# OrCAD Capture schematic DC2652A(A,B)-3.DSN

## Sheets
1 PAGE1: size Custom
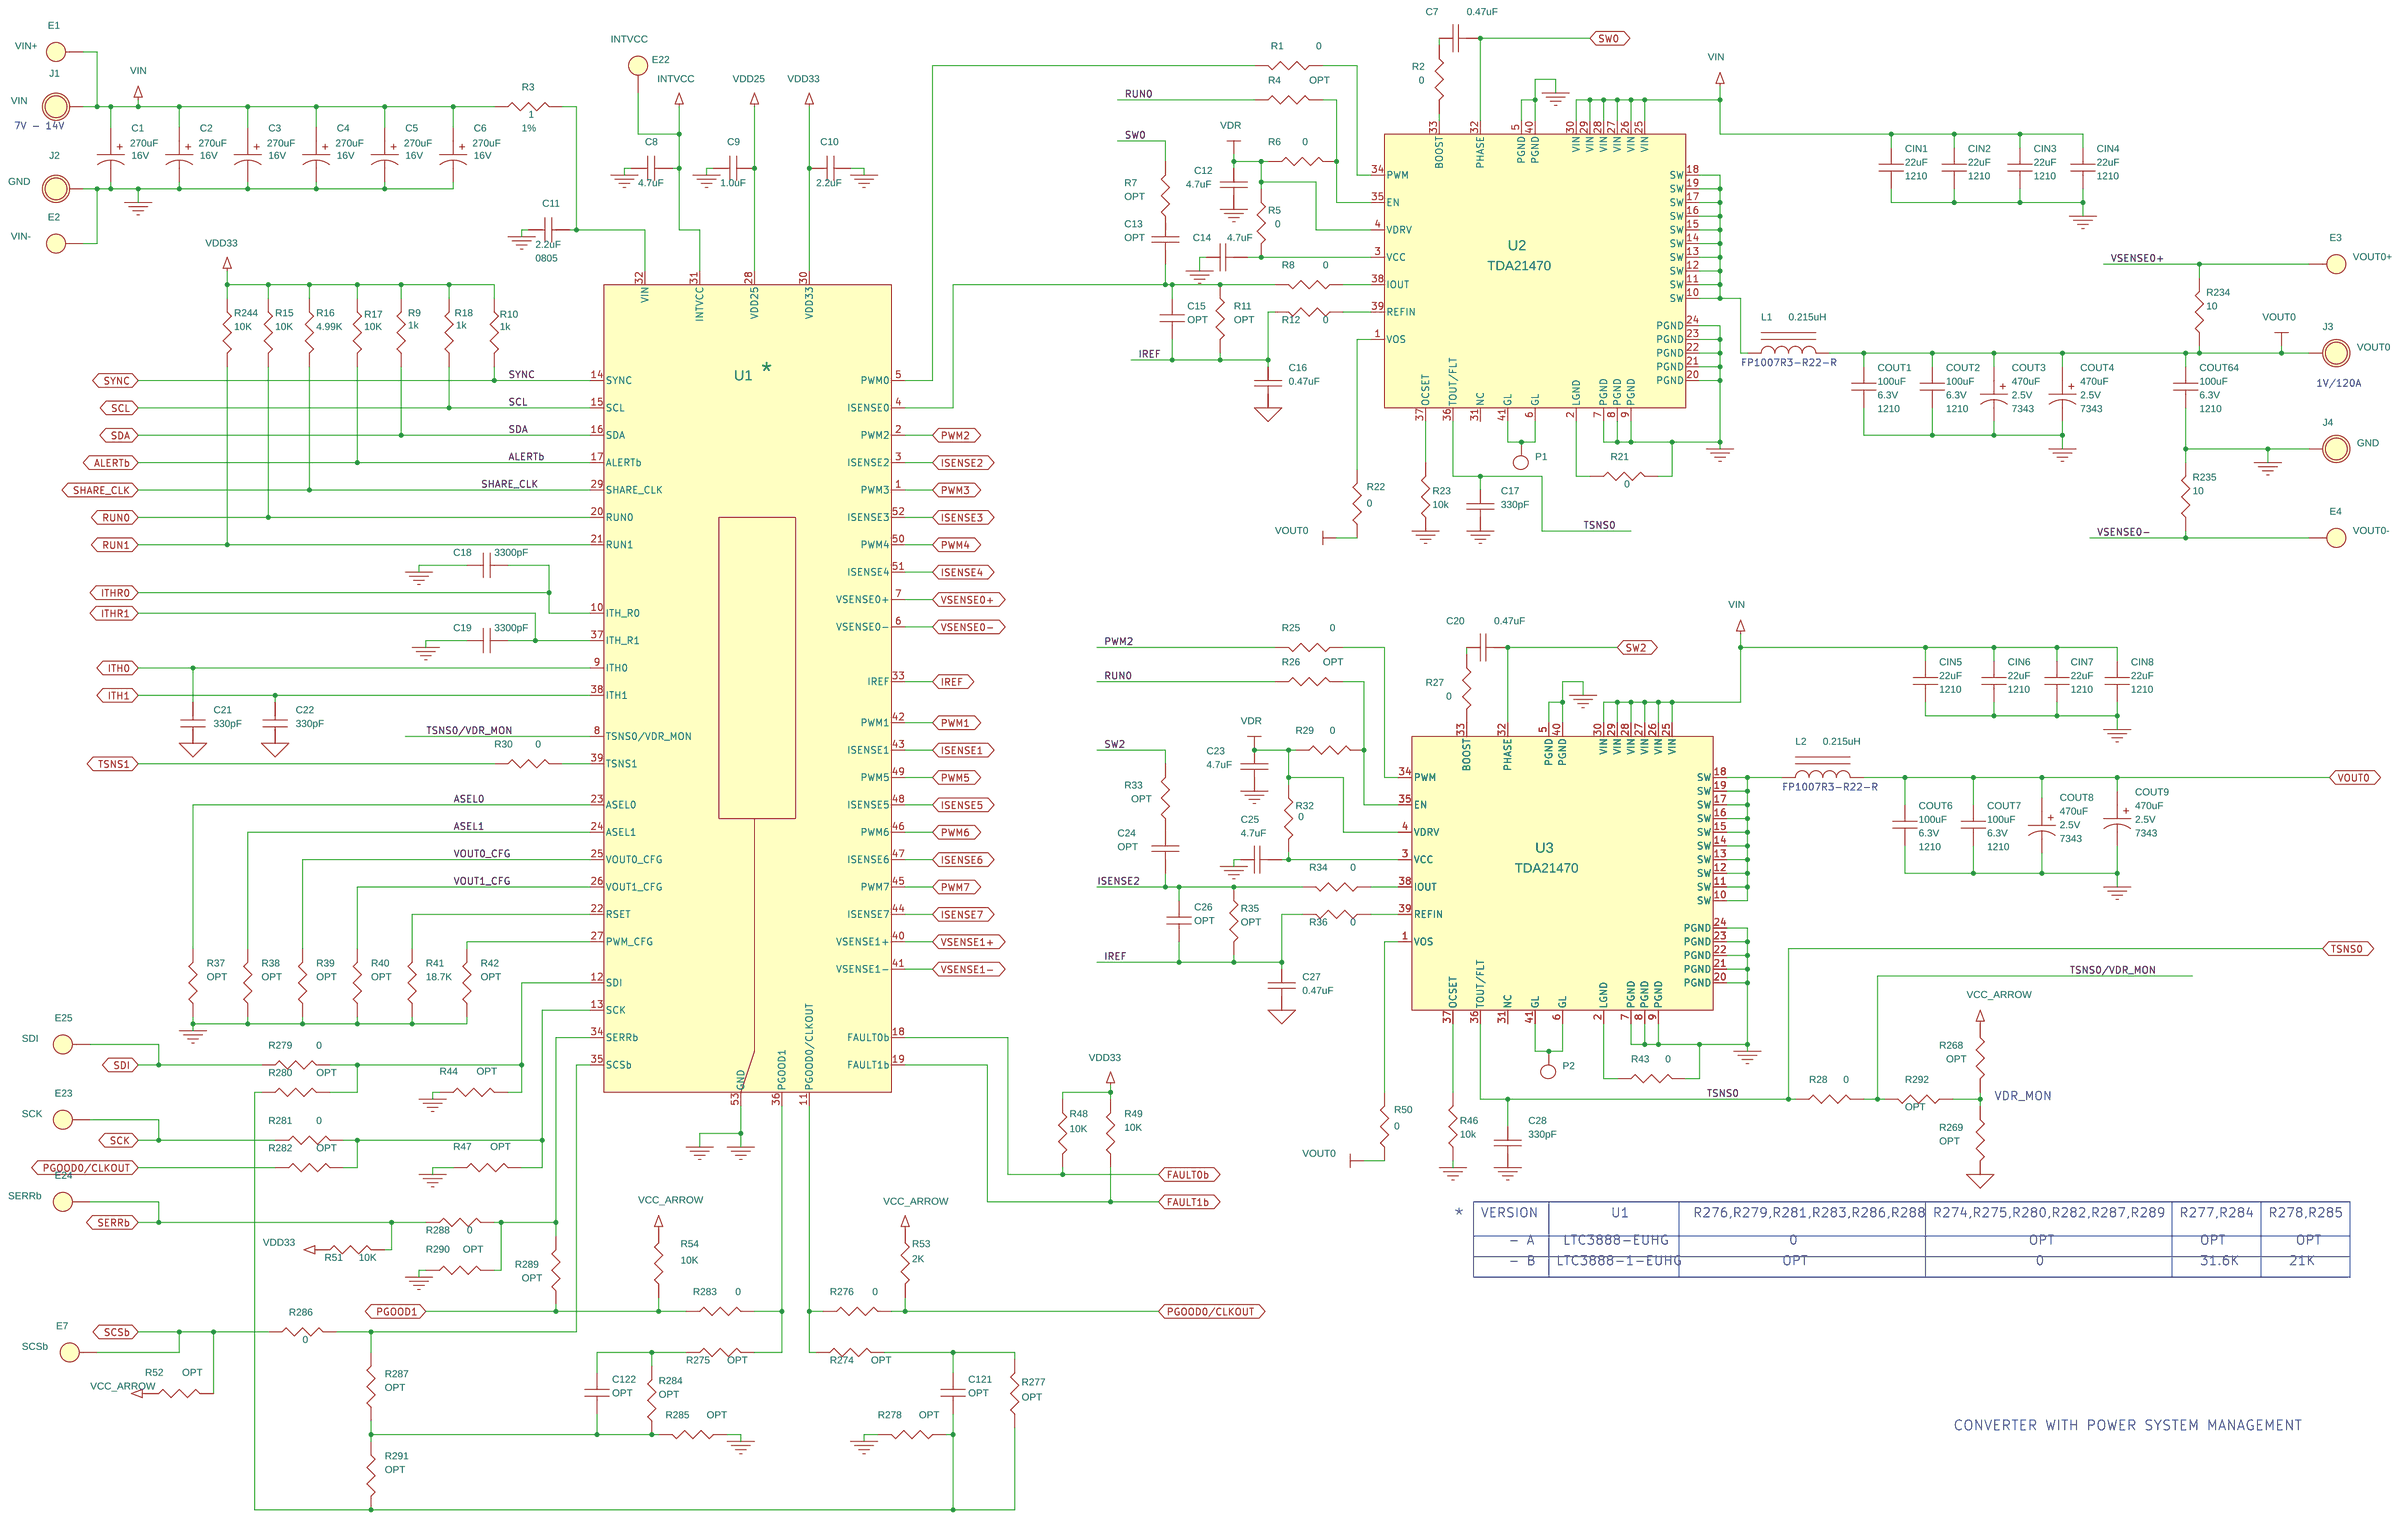
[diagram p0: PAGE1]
2 PAGE2: size Custom; note: 8-PHASE, DUAL OUTPUT SYNCHRONOUS BUCK
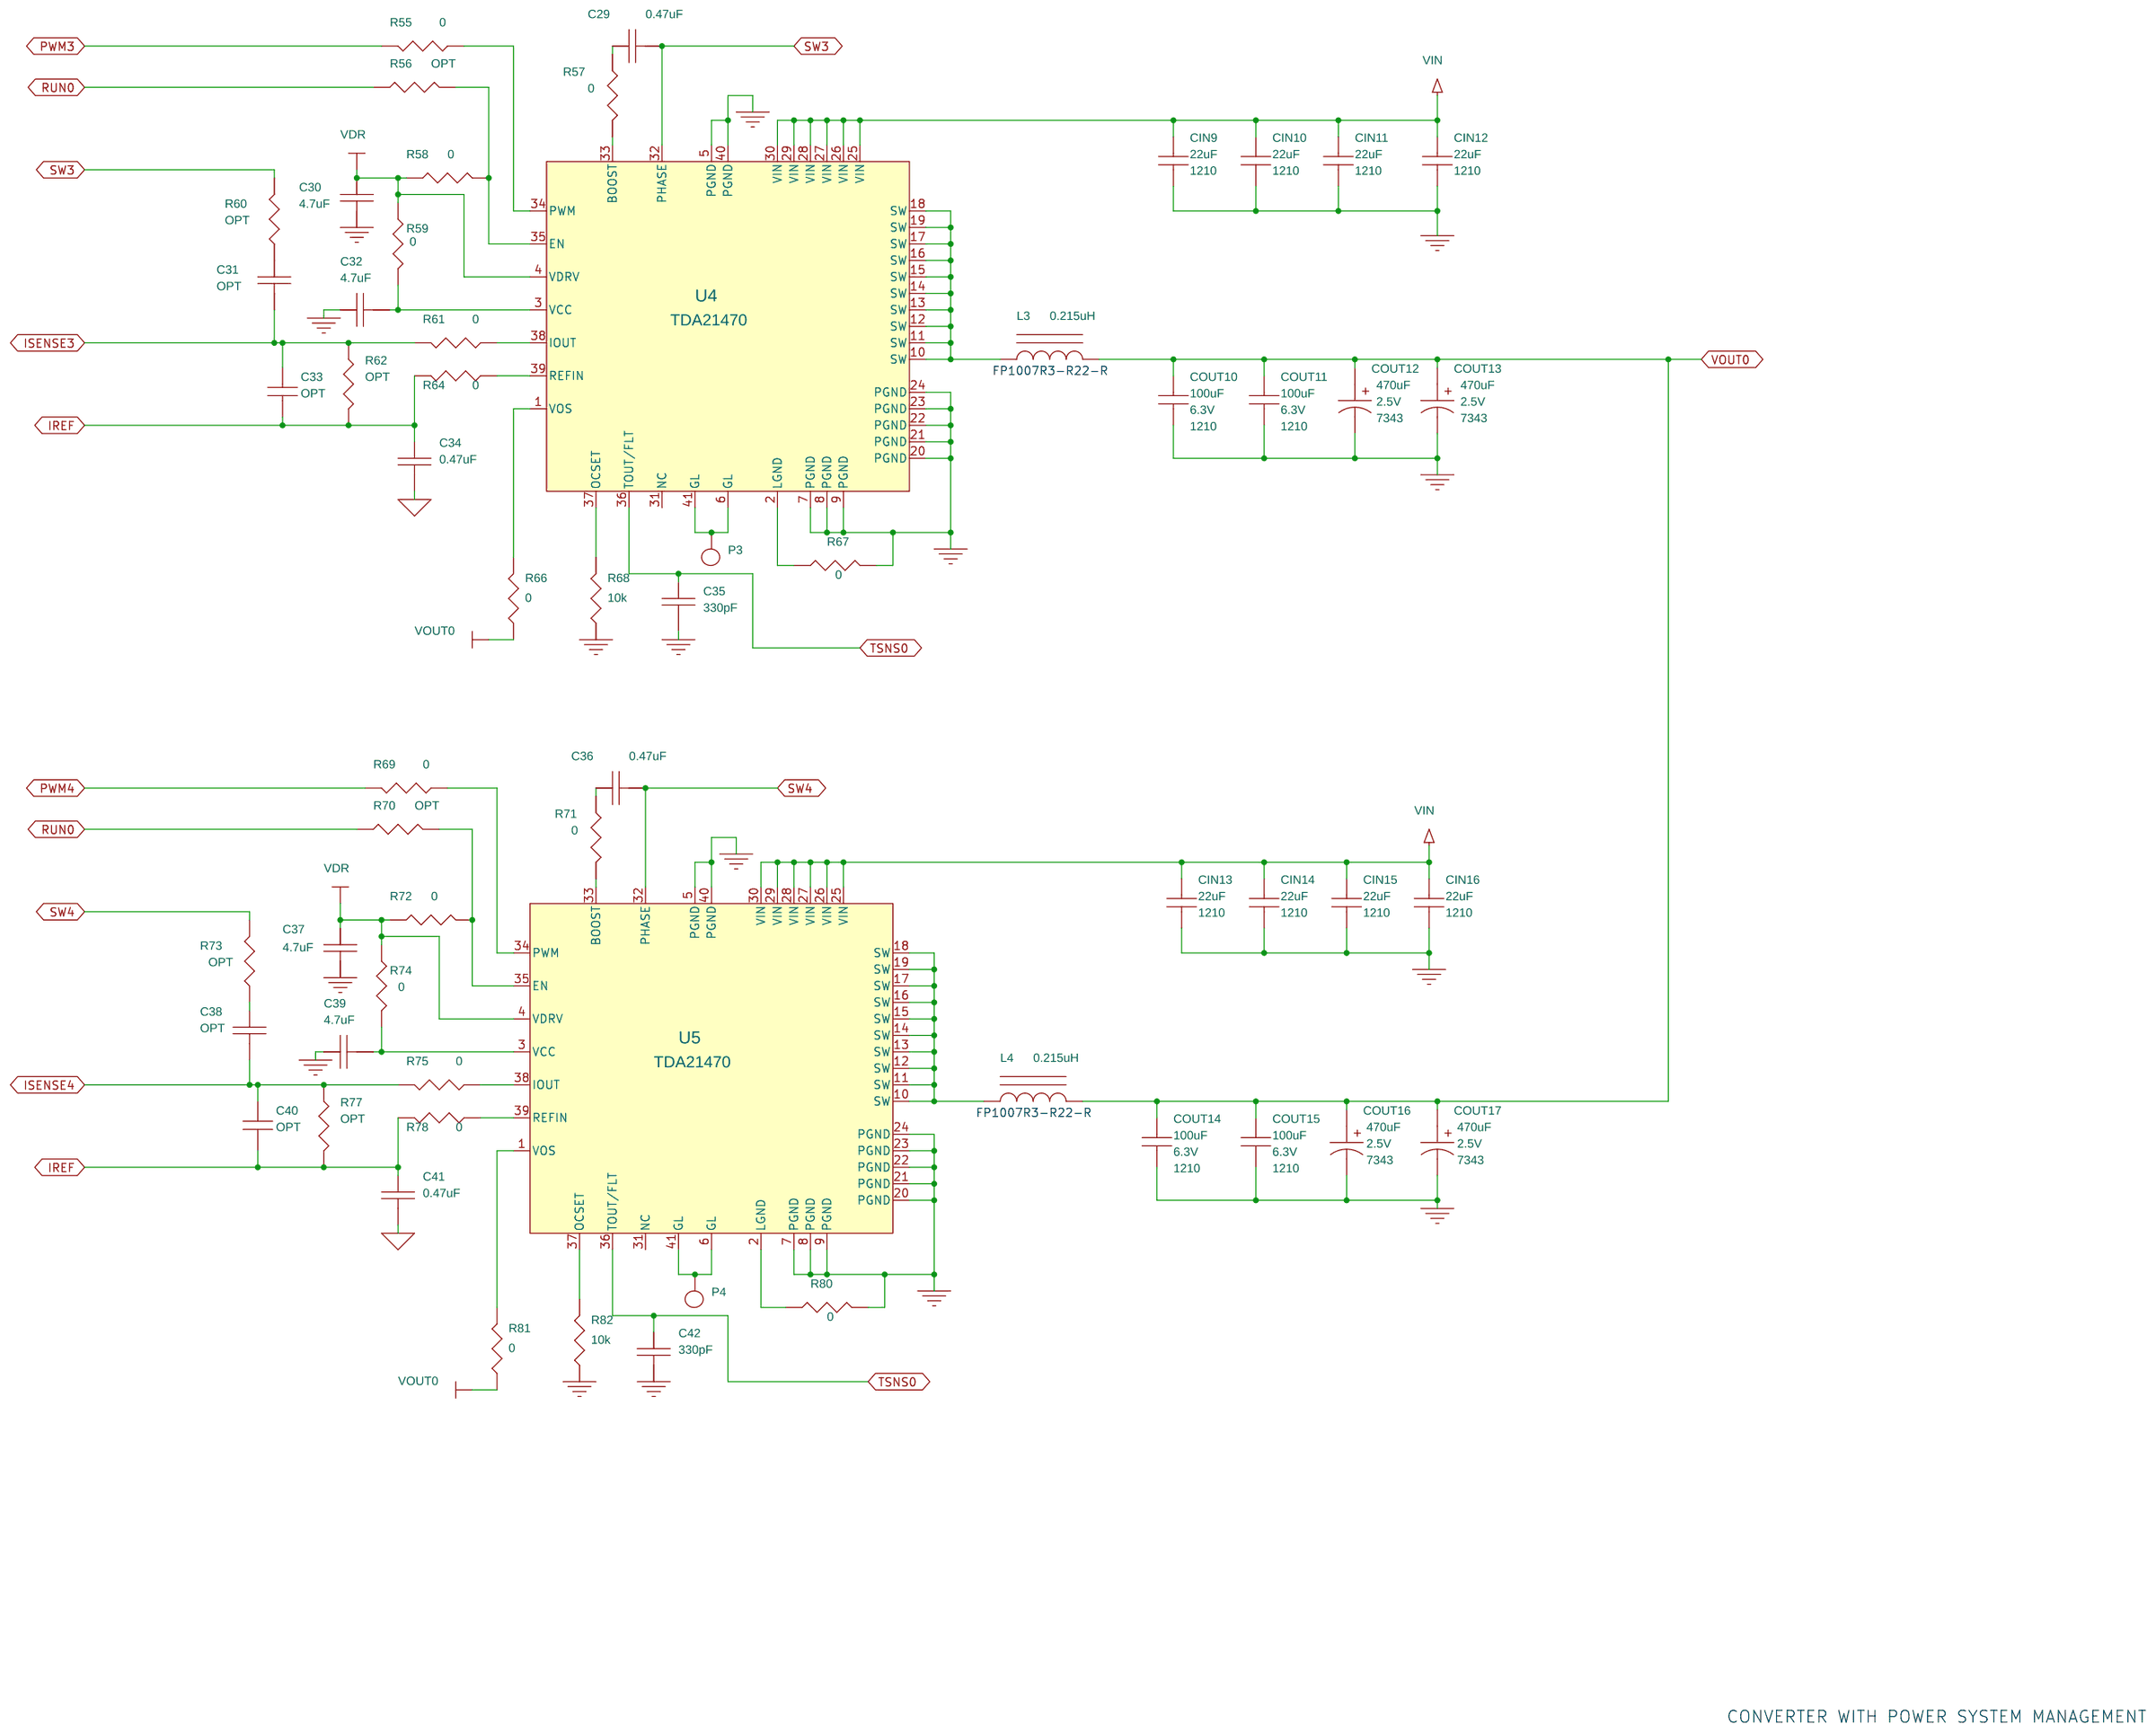
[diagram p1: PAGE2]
3 PAGE3: size Custom; note: 8-PHASE, DUAL OUTPUT SYNCHRONOUS BUCK
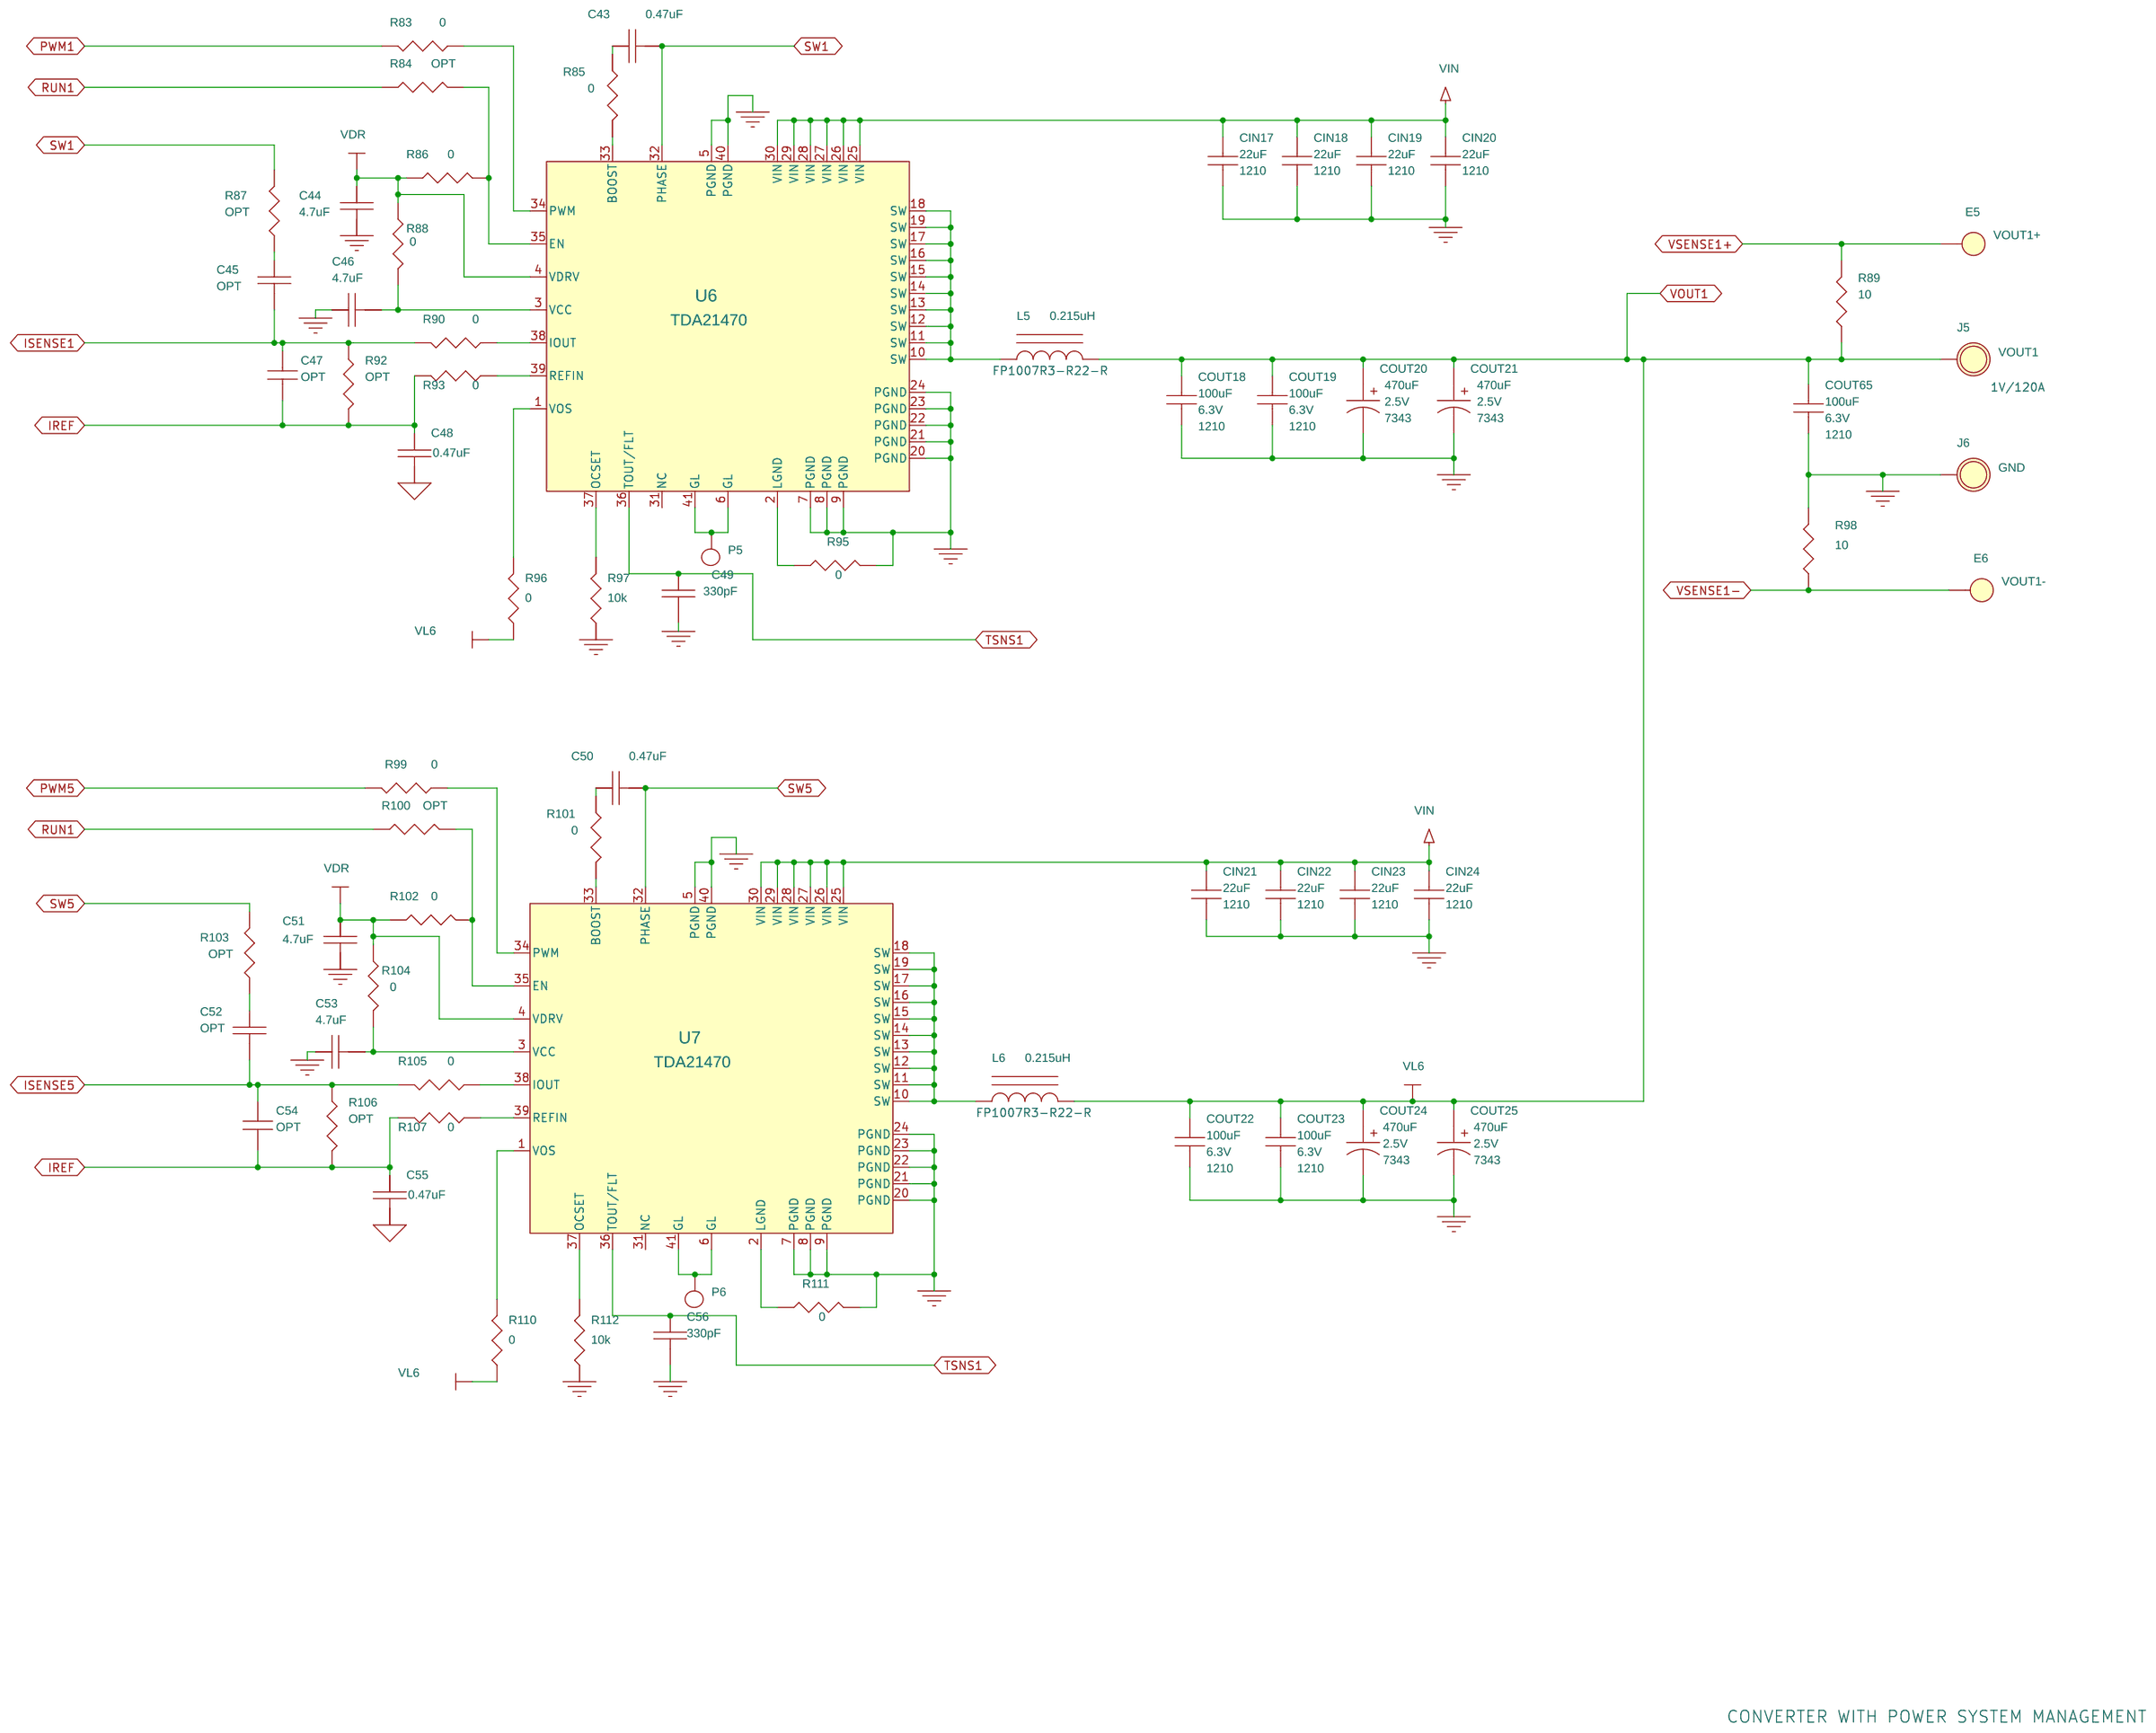
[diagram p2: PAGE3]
4 PAGE4: size Custom; note: 8-PHASE, DUAL OUTPUT SYNCHRONOUS BUCK
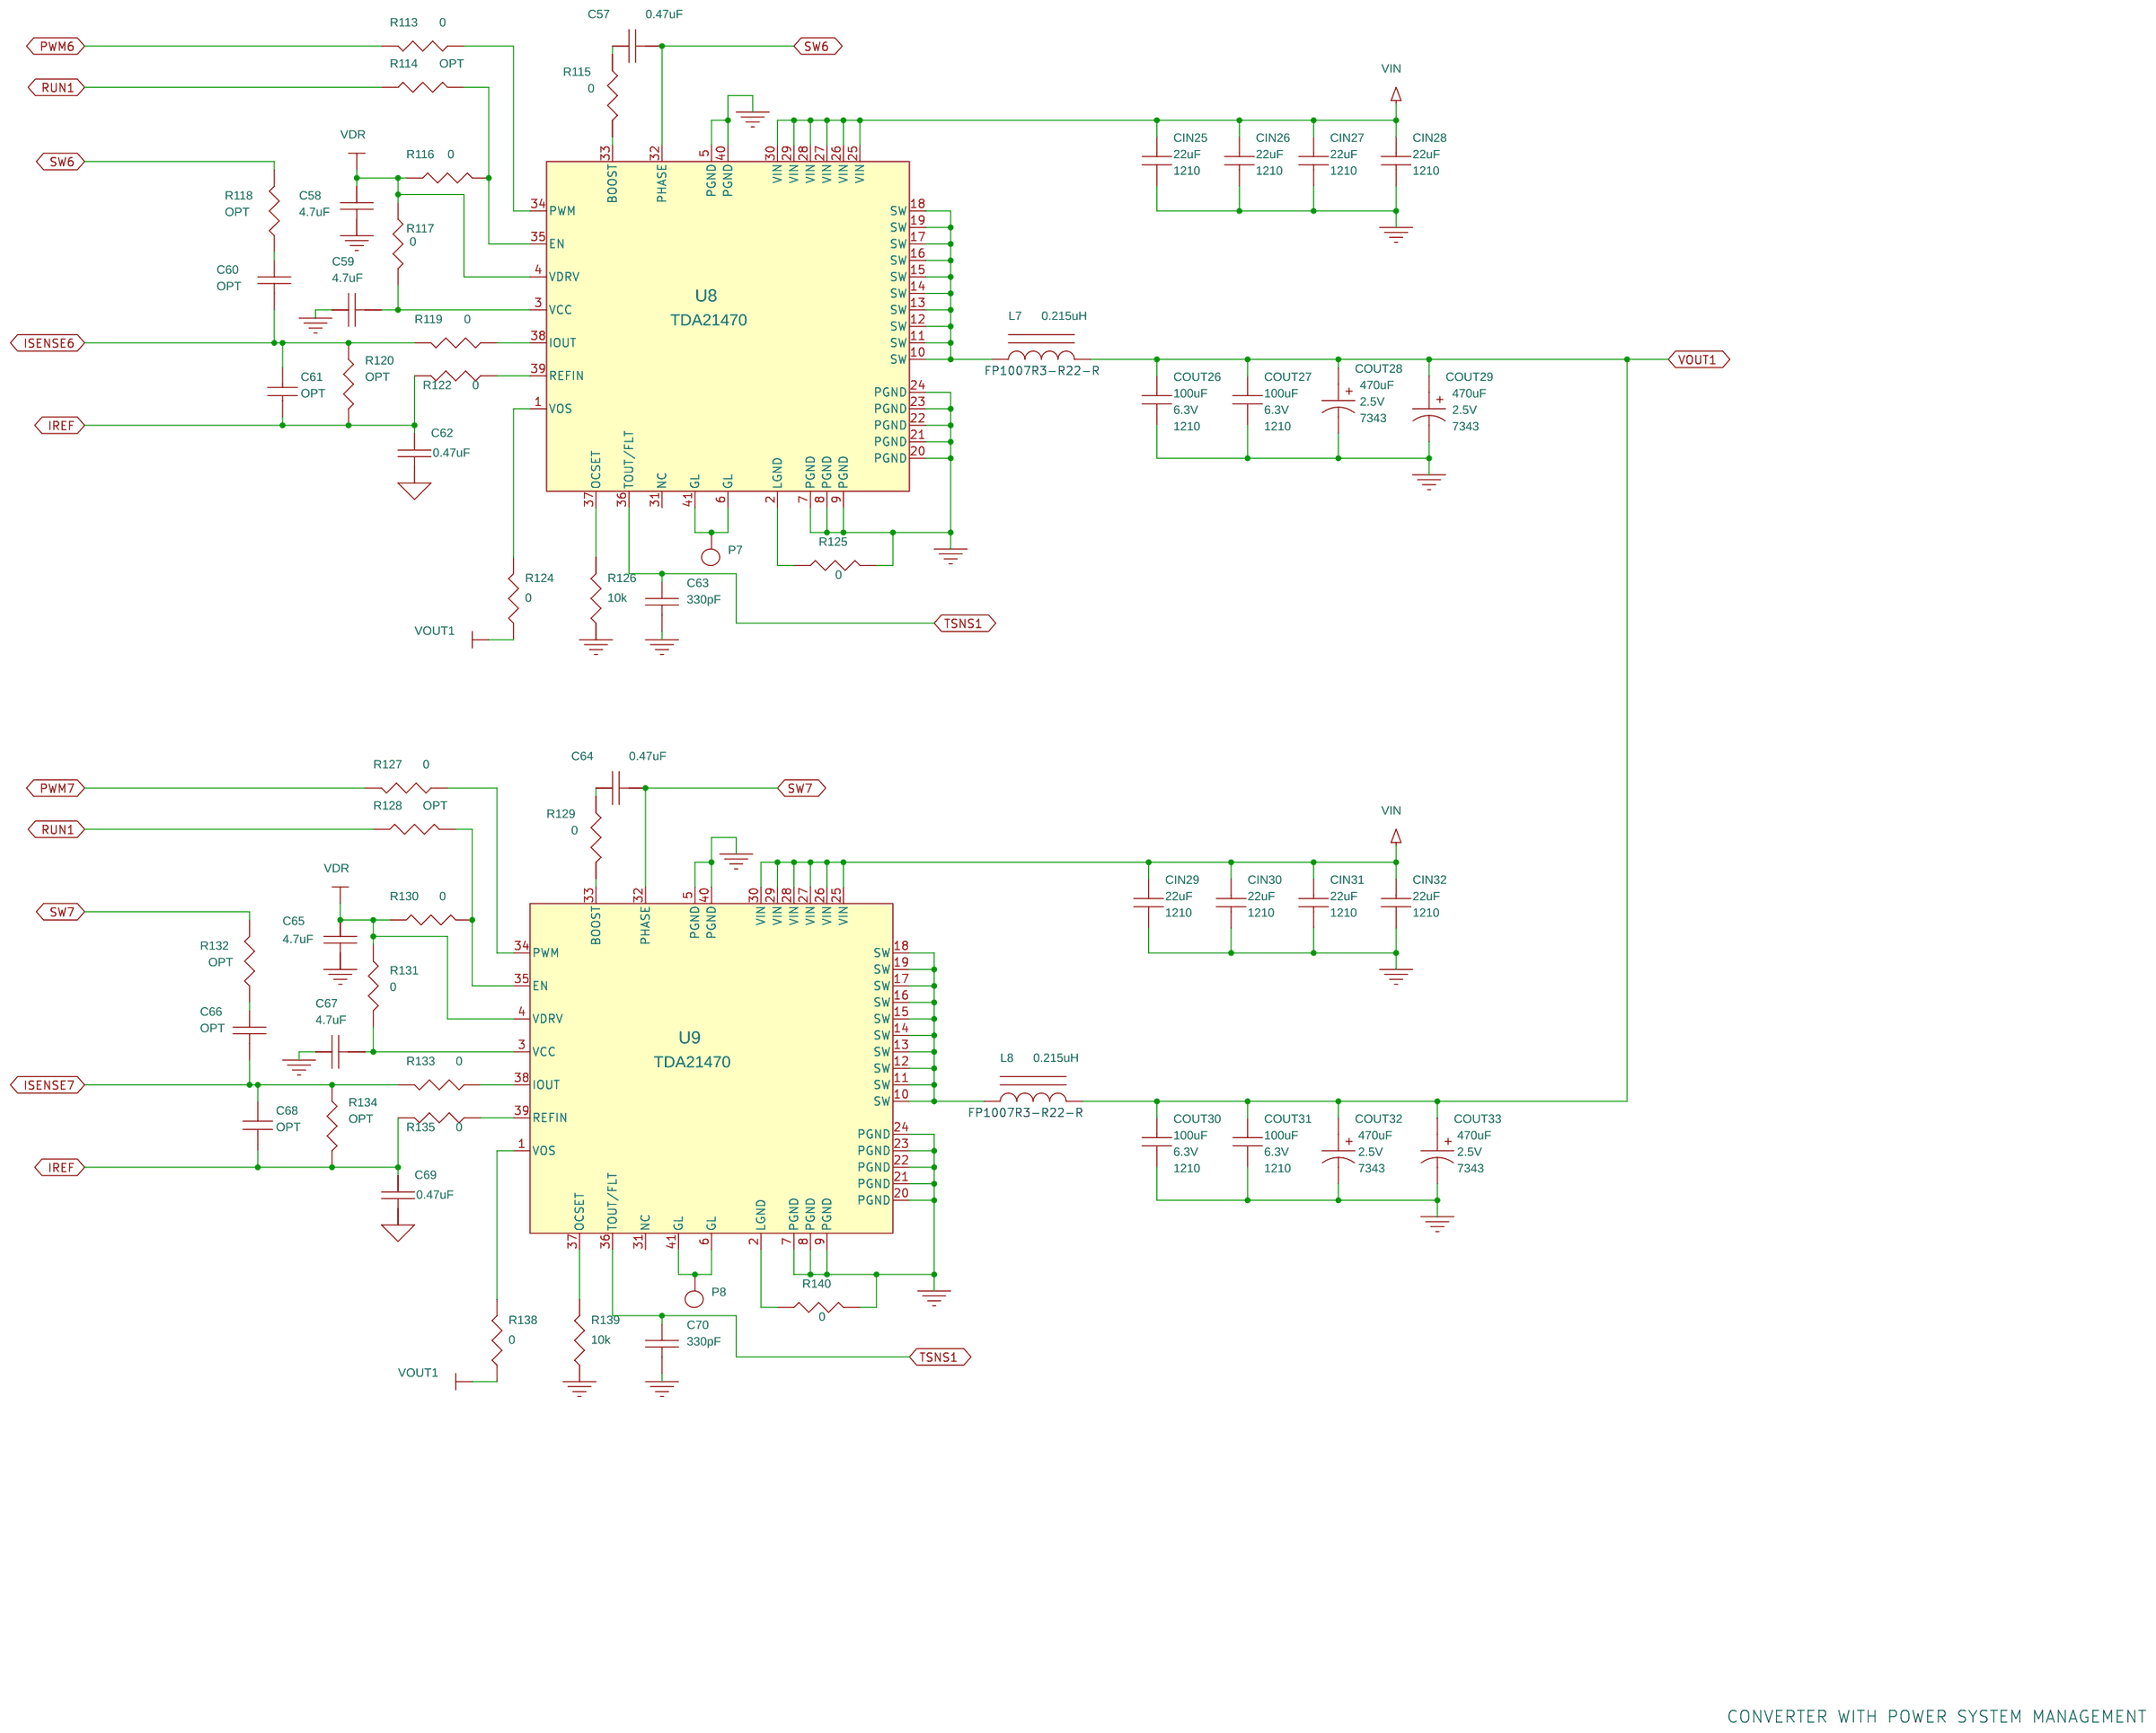
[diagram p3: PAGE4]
5 PAGE7: size Custom; note: 8-PHASE, DUAL OUTPUT SYNCHRONOUS BUCK
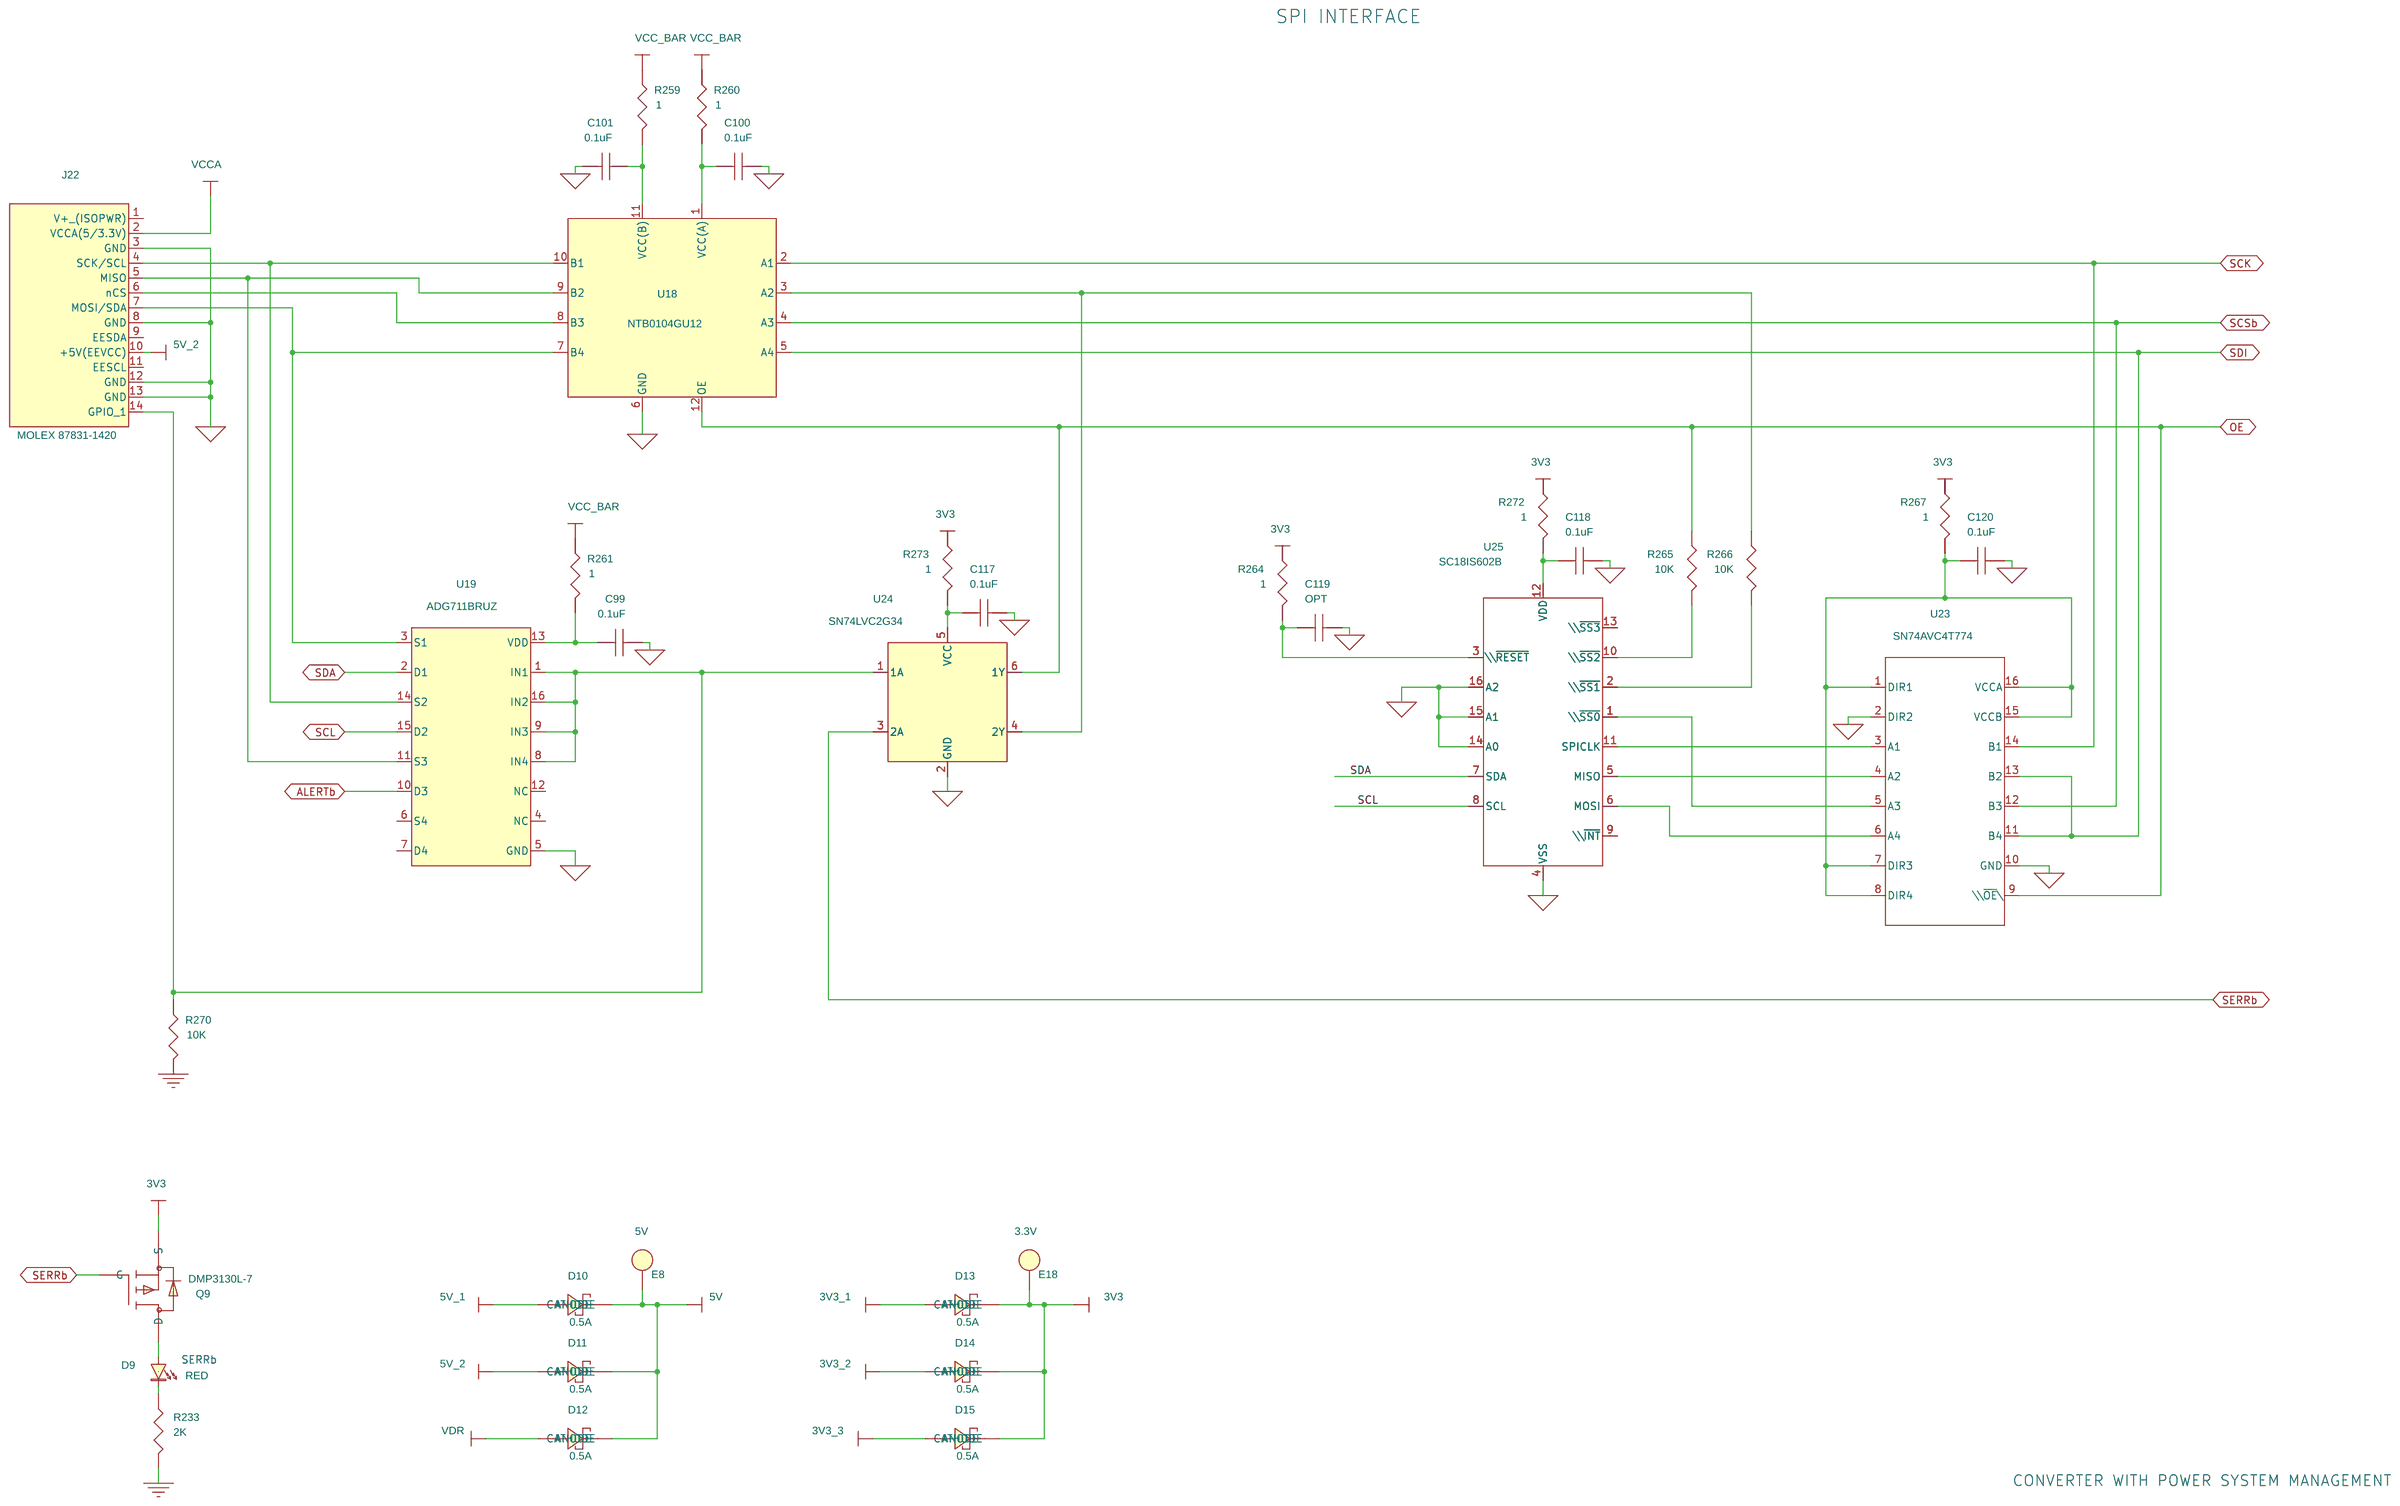
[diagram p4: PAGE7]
6 PAGE5: size Custom; note: 8-PHASE, DUAL OUTPUT SYNCHRONOUS BUCK
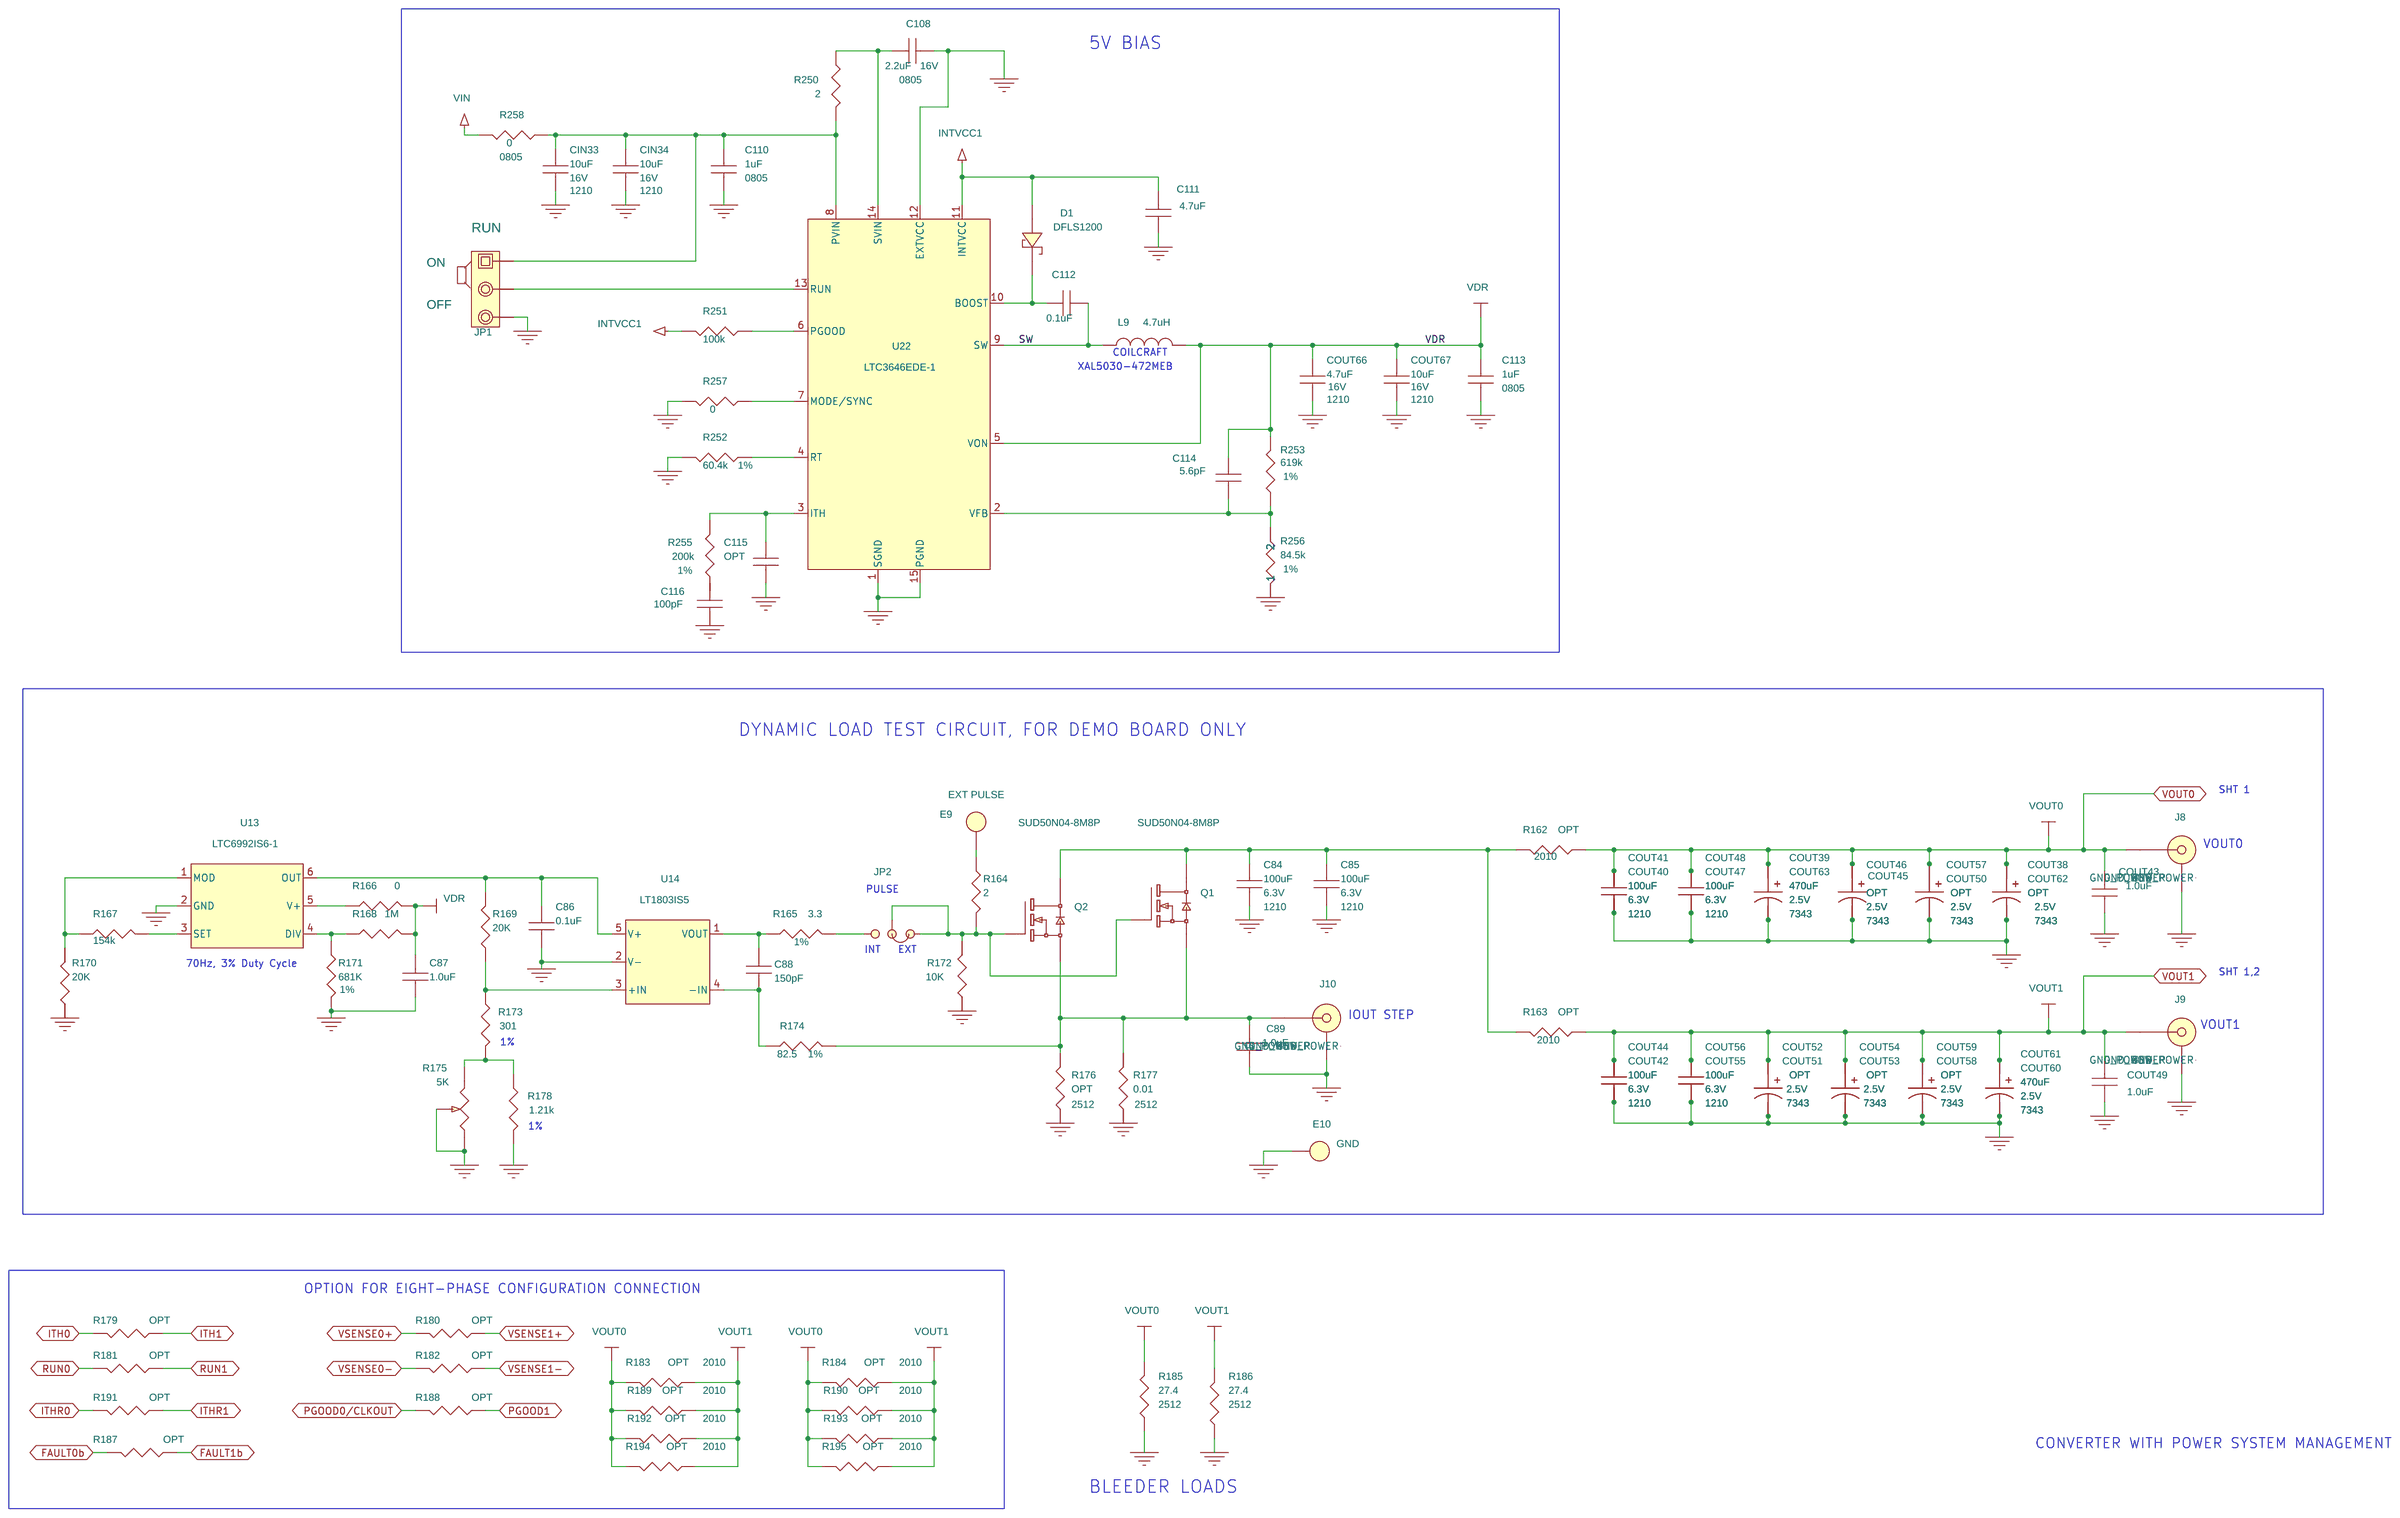
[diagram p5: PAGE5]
7 PAGE6: size Custom; note: 8-PHASE, DUAL OUTPUT SYNCHRONOUS BUCK
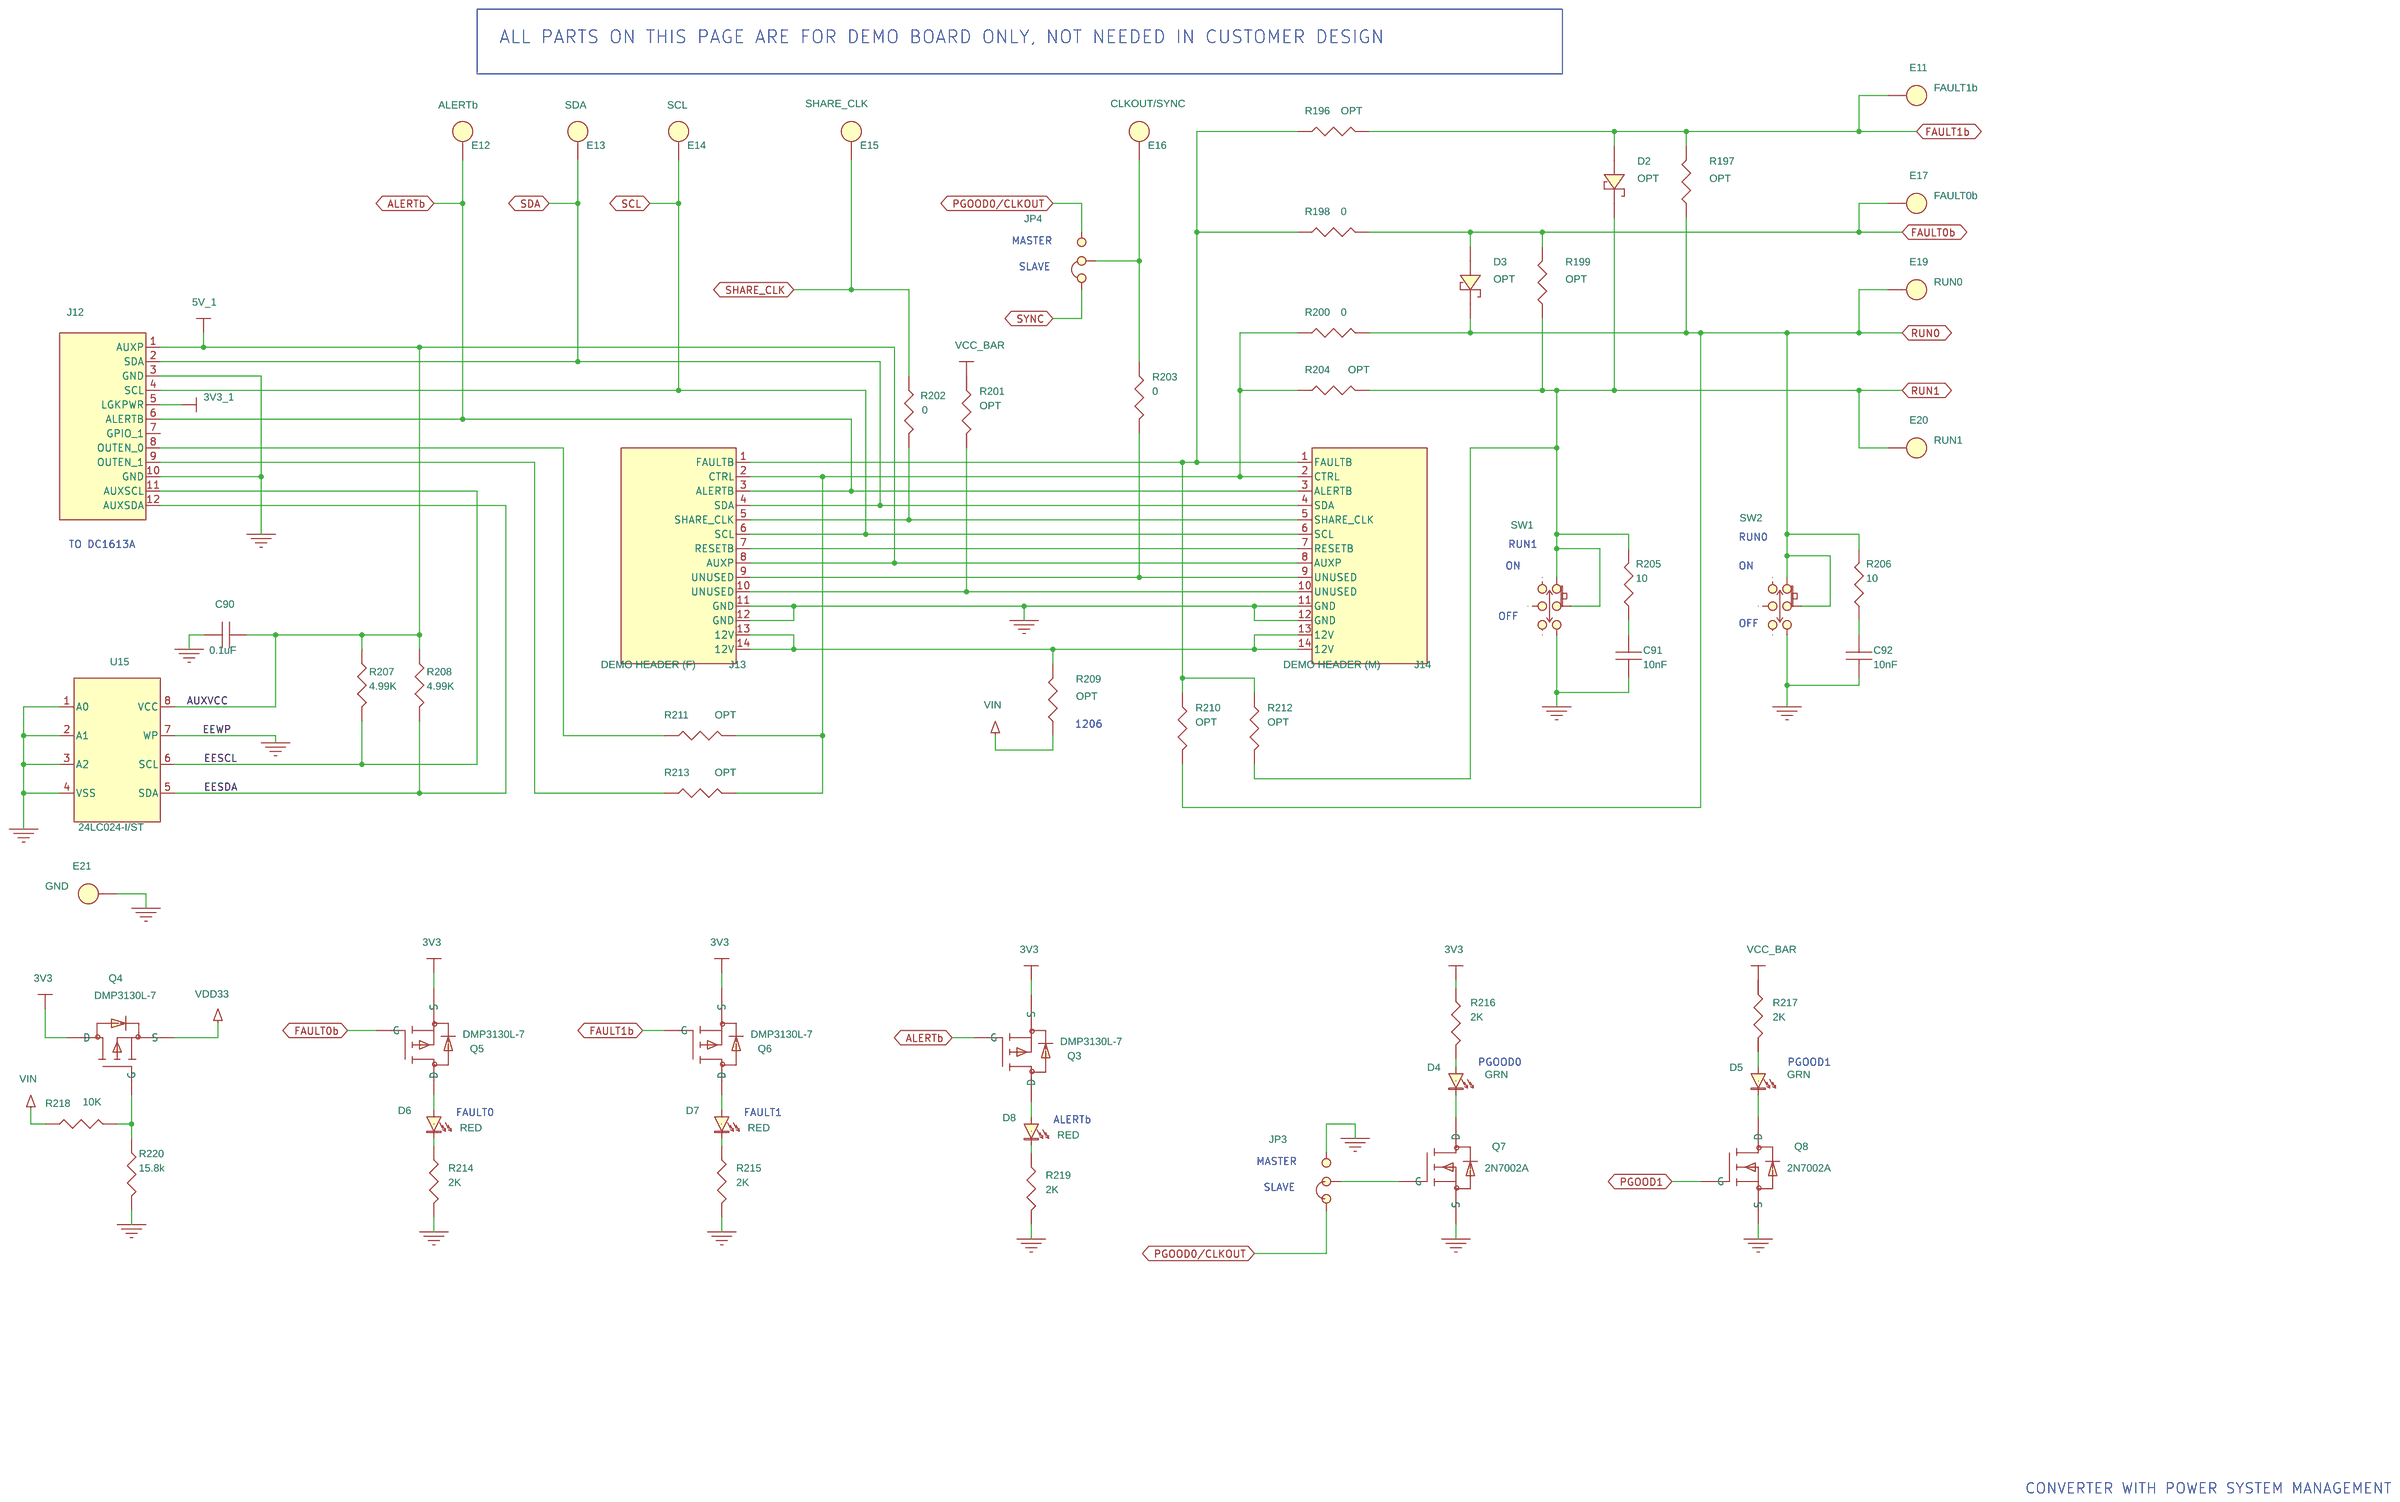
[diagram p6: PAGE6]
8 PAGE8: size Custom; note: 8-PHASE, DUAL OUTPUT SYNCHRONOUS BUCK
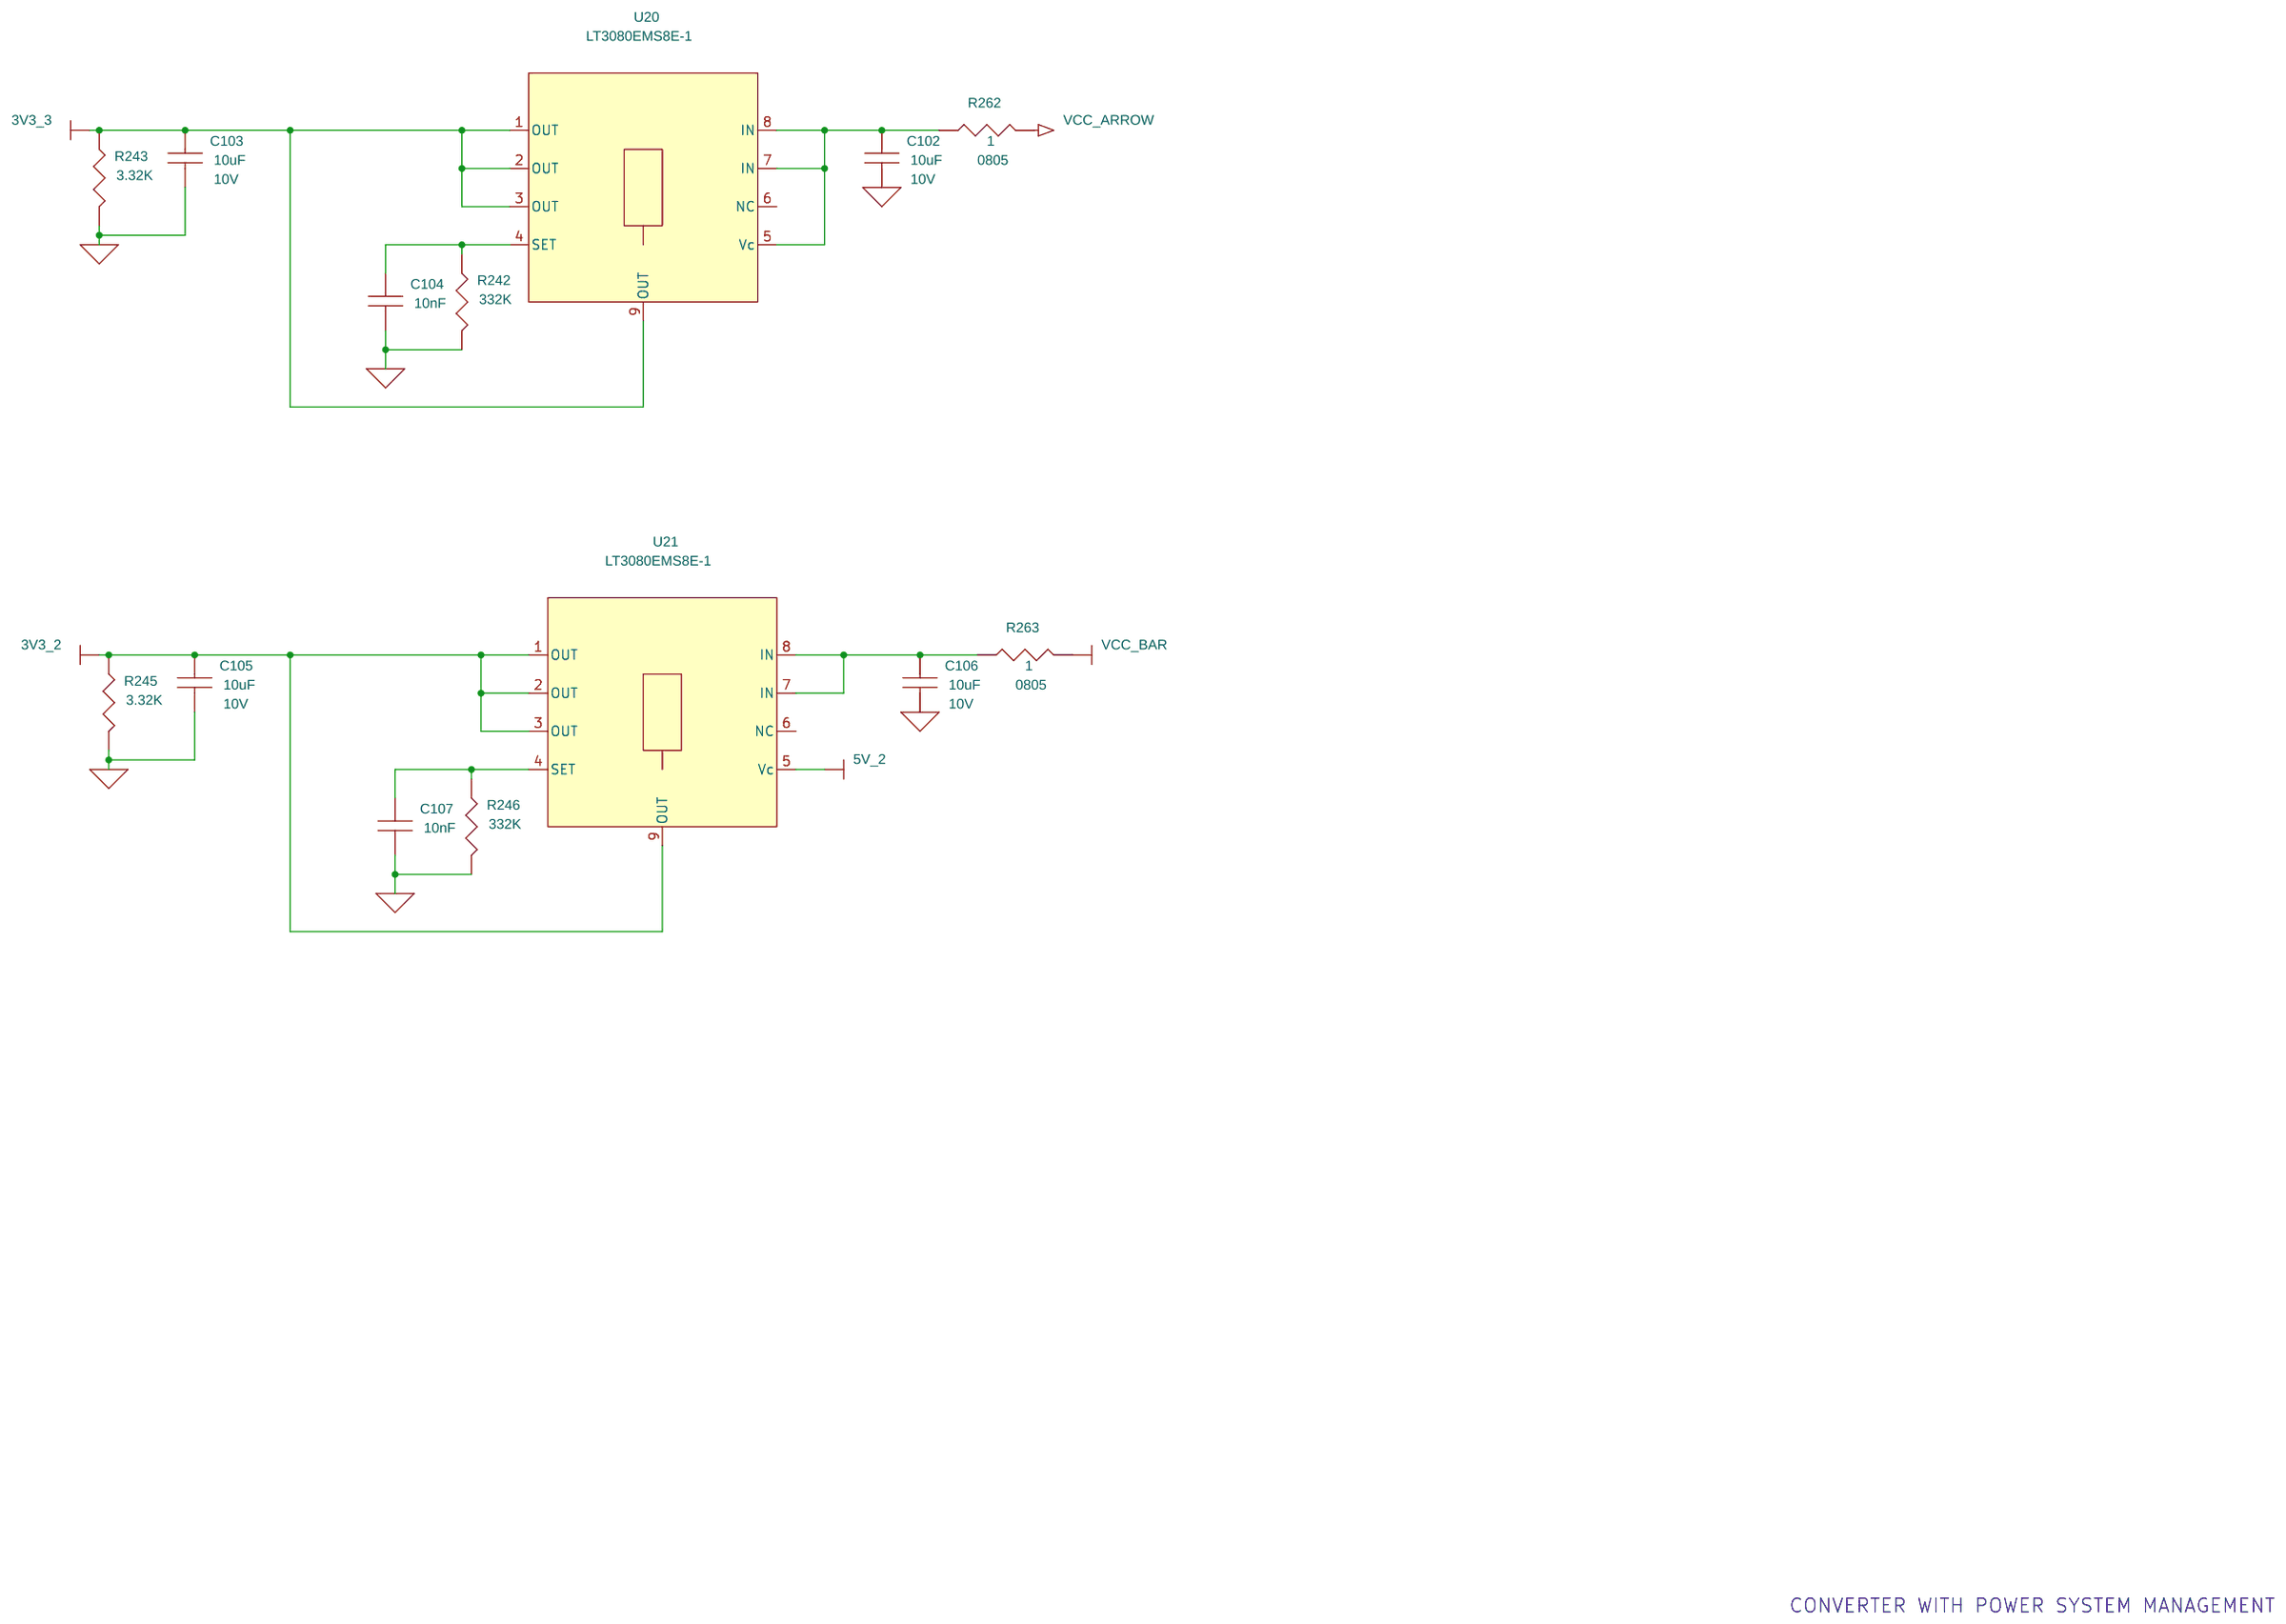
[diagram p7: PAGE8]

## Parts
sheet PAGE1
C1  270uF  [CAP-E12-8X12]
C2  270uF  [CAP-E12-8X12]
C3  270uF  [CAP-E12-8X12]
C4  270uF  [CAP-E12-8X12]
C5  270uF  [CAP-E12-8X12]
C6  270uF  [CAP-E12-8X12]
C7  0.47uF  [0402]
C8  4.7uF  [0603]
C9  1.0uF  [0603]
C10  2.2uF  [0603]
C11  2.2uF  [0805]
C12  4.7uF  [0402]
C13  OPT  [0402]
C14  4.7uF  [0402]
C15  OPT  [0603]
C16  0.47uF  [0402]
C17  330pF  [0402]
C18  3300pF  [CC0603N]
C19  3300pF  [CC0603N]
C20  0.47uF  [0402]
C21  330pF  [0603]
C22  330pF  [0603]
C23  4.7uF  [0402]
C24  OPT  [0402]
C25  4.7uF  [0402]
C26  OPT  [0603]
C27  0.47uF  [0402]
C28  330pF  [0402]
C121  OPT  [0603]
C122  OPT  [0603]
CIN1  22uF  [1210]
CIN2  22uF  [1210]
CIN3  22uF  [1210]
CIN4  22uF  [1210]
CIN5  22uF  [1210]
CIN6  22uF  [1210]
CIN7  22uF  [1210]
CIN8  22uF  [1210]
COUT1  100uF  [1210]
COUT2  100uF  [1210]
COUT3  470uF  [7343]
COUT4  470uF  [7343]
COUT6  100uF  [1210]
COUT7  100uF  [1210]
COUT8  470uF  [7343]
COUT9  470uF  [7343]
COUT64  100uF  [1210]
E1  VIN+  [TP\MMX\2501-2]
E2  VIN-  [TP\MMX\2501-2]
E3  VOUT0+  [TP\MMX\2501-2]
E4  VOUT0-  [TP\MMX\2501-2]
E7  SCSb  [TP\MMX\2501-2]
E22  INTVCC  [TP\MMX\2501-2]
E23  SCK  [TP\MMX\2501-2]
E24  SERRb  [TP\MMX\2501-2]
E25  SDI  [TP\MMX\2501-2]
J1  CON\LUG\10  [CON\LUG\10]
J2  CON\LUG\10  [CON\LUG\10]
J3  CON\LUG\10  [CON\LUG\10]
J4  CON\LUG\10  [CON\LUG\10]
L1  0.215uH  [IND\WURTH\7443010XX]
L2  0.215uH  [IND\WURTH\7443010XX]
P1  SMD PAD  [PAD]
P2  SMD PAD  [PAD]
R1  0  [0402]
R2  0  [0402]
R3  1  [0603]
R4  OPT  [0402]
R5  0  [0402]
R6  0  [0402]
R7  OPT  [0402]
R8  0  [0402]
R9  1k  [0603]
R10  1k  [0603]
R11  OPT  [0402]
R12  0  [0402]
R15  10K  [0603]
R16  4.99K  [0603]
R17  10K  [0603]
R18  1k  [0603]
R21  0  [0402]
R22  0  [0402]
R23  10k  [0402]
R25  0  [0402]
R26  OPT  [0402]
R27  0  [0402]
R28  0  [0603]
R29  0  [0402]
R30  0  [0603]
R32  0  [0402]
R33  OPT  [0402]
R34  0  [0402]
R35  OPT  [0402]
R36  0  [0402]
R37  OPT  [0603]
R38  OPT  [0603]
R39  OPT  [0603]
R40  OPT  [0603]
R41  18.7K  [0603]
R42  OPT  [0603]
R43  0  [0402]
R44  OPT  [0603]
R46  10k  [0402]
R47  OPT  [0603]
R48  10K  [0603]
R49  10K  [0603]
R50  0  [0402]
R51  10K  [0603]
R52  OPT  [0603]
R53  2K  [0603]
R54  10K  [0603]
R234  10  [0603]
R235  10  [0603]
R244  10K  [0603]
R268  OPT  [0603]
R269  OPT  [0603]
R274  OPT  [0603]
R275  OPT  [0603]
R276  0  [0603]
R277  OPT  [0603]
R278  OPT  [0603]
R279  0  [0603]
R280  OPT  [0603]
R281  0  [0603]
R282  OPT  [0603]
R283  0  [0603]
R284  OPT  [0603]
R285  OPT  [0603]
R286  0  [0603]
R287  OPT  [0603]
R288  0  [0603]
R289  OPT  [0603]
R290  OPT  [0603]
R291  OPT  [0603]
R292  OPT  [0603]
U1  *  [LTC-UHG-52-1550]
U2  TDA21470  [IR35411]
U3  TDA21470  [IR35411]
sheet PAGE2
C29  0.47uF  [0402]
C30  4.7uF  [0402]
C31  OPT  [0402]
C32  4.7uF  [0402]
C33  OPT  [0603]
C34  0.47uF  [0402]
C35  330pF  [0402]
C36  0.47uF  [0402]
C37  4.7uF  [0402]
C38  OPT  [0402]
C39  4.7uF  [0402]
C40  OPT  [0603]
C41  0.47uF  [0402]
C42  330pF  [0402]
CIN9  22uF  [1210]
CIN10  22uF  [1210]
CIN11  22uF  [1210]
CIN12  22uF  [1210]
CIN13  22uF  [1210]
CIN14  22uF  [1210]
CIN15  22uF  [1210]
CIN16  22uF  [1210]
COUT10  100uF  [1210]
COUT11  100uF  [1210]
COUT12  470uF  [7343]
COUT13  470uF  [7343]
COUT14  100uF  [1210]
COUT15  100uF  [1210]
COUT16  470uF  [7343]
COUT17  470uF  [7343]
L3  0.215uH  [IND\WURTH\7443010XX]
L4  0.215uH  [IND\WURTH\7443010XX]
P3  SMD PAD  [PAD]
P4  SMD PAD  [PAD]
R55  0  [0402]
R56  OPT  [0402]
R57  0  [0402]
R58  0  [0402]
R59  0  [0402]
R60  OPT  [0402]
R61  0  [0402]
R62  OPT  [0402]
R64  0  [0402]
R66  0  [0402]
R67  0  [0402]
R68  10k  [0402]
R69  0  [0402]
R70  OPT  [0402]
R71  0  [0402]
R72  0  [0402]
R73  OPT  [0402]
R74  0  [0402]
R75  0  [0402]
R77  OPT  [0402]
R78  0  [0402]
R80  0  [0402]
R81  0  [0402]
R82  10k  [0402]
U4  TDA21470  [IR35411]
U5  TDA21470  [IR35411]
sheet PAGE3
C43  0.47uF  [0402]
C44  4.7uF  [0402]
C45  OPT  [0402]
C46  4.7uF  [0402]
C47  OPT  [0603]
C48  0.47uF  [0402]
C49  330pF  [0402]
C50  0.47uF  [0402]
C51  4.7uF  [0402]
C52  OPT  [0402]
C53  4.7uF  [0402]
C54  OPT  [0603]
C55  0.47uF  [0402]
C56  330pF  [0402]
CIN17  22uF  [1210]
CIN18  22uF  [1210]
CIN19  22uF  [1210]
CIN20  22uF  [1210]
CIN21  22uF  [1210]
CIN22  22uF  [1210]
CIN23  22uF  [1210]
CIN24  22uF  [1210]
COUT18  100uF  [1210]
COUT19  100uF  [1210]
COUT20  470uF  [7343]
COUT21  470uF  [7343]
COUT22  100uF  [1210]
COUT23  100uF  [1210]
COUT24  470uF  [7343]
COUT25  470uF  [7343]
COUT65  100uF  [1210]
E5  VOUT1+  [TP\MMX\2501-2]
E6  VOUT1-  [TP\MMX\2501-2]
J5  CON\LUG\10  [CON\LUG\10]
J6  CON\LUG\10  [CON\LUG\10]
L5  0.215uH  [IND\WURTH\7443010XX]
L6  0.215uH  [IND\WURTH\7443010XX]
P5  SMD PAD  [PAD]
P6  SMD PAD  [PAD]
R83  0  [0402]
R84  OPT  [0402]
R85  0  [0402]
R86  0  [0402]
R87  OPT  [0402]
R88  0  [0402]
R89  10  [0603]
R90  0  [0402]
R92  OPT  [0402]
R93  0  [0402]
R95  0  [0402]
R96  0  [0402]
R97  10k  [0402]
R98  10  [0603]
R99  0  [0402]
R100  OPT  [0402]
R101  0  [0402]
R102  0  [0402]
R103  OPT  [0402]
R104  0  [0402]
R105  0  [0402]
R106  OPT  [0402]
R107  0  [0402]
R110  0  [0402]
R111  0  [0402]
R112  10k  [0402]
U6  TDA21470  [IR35411]
U7  TDA21470  [IR35411]
sheet PAGE4
C57  0.47uF  [0402]
C58  4.7uF  [0402]
C59  4.7uF  [0402]
C60  OPT  [0402]
C61  OPT  [0603]
C62  0.47uF  [0402]
C63  330pF  [0402]
C64  0.47uF  [0402]
C65  4.7uF  [0402]
C66  OPT  [0402]
C67  4.7uF  [0402]
C68  OPT  [0603]
C69  0.47uF  [0402]
C70  330pF  [0402]
CIN25  22uF  [1210]
CIN26  22uF  [1210]
CIN27  22uF  [1210]
CIN28  22uF  [1210]
CIN29  22uF  [1210]
CIN30  22uF  [1210]
CIN31  22uF  [1210]
CIN32  22uF  [1210]
COUT26  100uF  [1210]
COUT27  100uF  [1210]
COUT28  470uF  [7343]
COUT29  470uF  [7343]
COUT30  100uF  [1210]
COUT31  100uF  [1210]
COUT32  470uF  [7343]
COUT33  470uF  [7343]
L7  0.215uH  [IND\WURTH\7443010XX]
L8  0.215uH  [IND\WURTH\7443010XX]
P7  SMD PAD  [PAD]
P8  SMD PAD  [PAD]
R113  0  [0402]
R114  OPT  [0402]
R115  0  [0402]
R116  0  [0402]
R117  0  [0402]
R118  OPT  [0402]
R119  0  [0402]
R120  OPT  [0402]
R122  0  [0402]
R124  0  [0402]
R125  0  [0402]
R126  10k  [0402]
R127  0  [0402]
R128  OPT  [0402]
R129  0  [0402]
R130  0  [0402]
R131  0  [0402]
R132  OPT  [0402]
R133  0  [0402]
R134  OPT  [0402]
R135  0  [0402]
R138  0  [0402]
R139  10k  [0402]
R140  0  [0402]
U8  TDA21470  [IR35411]
U9  TDA21470  [IR35411]
sheet PAGE5
C84  100uF  [1210]
C85  100uF  [1210]
C86  0.1uF  [0603]
C87  1.0uF  [0603]
C88  150pF  [0603]
C89  1.0uF  [0603]
C108  2.2uF  [0805]
C110  1uF  [0805]
C111  4.7uF  [C0603]
C112  0.1uF  [C0603]
C113  1uF  [0805]
C114  5.6pF  [0603]
C115  OPT  [0603]
C116  100pF  [0603]
CIN33  10uF  [C1210]
CIN34  10uF  [C1210]
COUT38  OPT  [7343]
COUT39  470uF  [CAPMP7343N]
COUT40  100uF  [1210]
COUT41  100uF  [1210]
COUT42  100uF  [1210]
COUT43  1.0uF  [0603]
COUT44  100uF  [1210]
COUT45  OPT  [7343]
COUT46  OPT  [7343]
COUT47  100uF  [1210]
COUT48  100uF  [1210]
COUT49  1.0uF  [0603]
COUT50  OPT  [7343]
COUT51  OPT  [7343]
COUT52  OPT  [7343]
COUT53  OPT  [7343]
COUT54  OPT  [7343]
COUT55  100uF  [1210]
COUT56  100uF  [1210]
COUT57  OPT  [7343]
COUT58  OPT  [7343]
COUT59  OPT  [7343]
COUT60  470uF  [CAPMP7343N]
COUT61  470uF  [CAPMP7343N]
COUT62  OPT  [7343]
COUT63  470uF  [CAPMP7343N]
COUT66  4.7uF  [C1210]
COUT67  10uF  [C1210]
D1  DFLS1200  [POWERDI_123]
E9  EXT PULSE  [TP\MMX\2501-2]
E10  GND  [TP\MMX\2501-2]
J8  XXX  [BNC5]
J9  XXX  [BNC5]
J10  XXX  [BNC5]
JP1  3 Pins 2mm Ctrs.  [SIP\3P\2MM]
JP2  JP3X1/079\NO\12  [SIP\3P\2MM]
L9  4.7uH  [IND\CLCRF_XAL5030-472]
Q1  SUD50N04-8M8P  [TO-252]
Q2  SUD50N04-8M8P  [TO-252]
R162  OPT  [2010]
R163  OPT  [2010]
R164  2  [0603]
R165  3.3  [0603]
R166  0  [0603]
R167  154k  [0603]
R168  1M  [0603]
R169  20K  [0603]
R170  20K  [0603]
R171  681K  [0603]
R172  10K  [0603]
R173  301  [0603]
R174  82.5  [0603]
R175  5K  [BOURNS_3386P]
R176  OPT  [2512]
R177  0.01  [2512]
R178  1.21k  [0603]
R179  OPT  [0603]
R180  OPT  [0603]
R181  OPT  [0603]
R182  OPT  [0603]
R183  OPT  [2010]
R184  OPT  [2010]
R185  27.4  [2512]
R186  27.4  [2512]
R187  OPT  [0603]
R188  OPT  [0603]
R189  OPT  [2010]
R190  OPT  [2010]
R191  OPT  [0603]
R192  OPT  [2010]
R193  OPT  [2010]
R194  OPT  [2010]
R195  OPT  [2010]
R250  2  [0603]
R251  100k  [0603]
R252  60.4k  [0603]
R253  619k  [0603]
R255  200k  [0603]
R256  84.5k  [0603]
R257  0  [0603]
R258  0  [0805]
U13  LTC6992IS6-1  [LT_S6]
U14  LT1803IS5  [LT_S5]
U22  LTC3646EDE-1  [LT_DE14_4x3]
XJP2  SHUNT  [NONE]
XJP5  2mm Ctrs.
sheet PAGE6
C90  0.1uF  [0603]
C91  10nF  [0603]
C92  10nF  [0603]
D2  OPT  [SOD323]
D3  OPT  [SOD323]
D4  GRN  [WURTH_LED]
D5  GRN  [WURTH_LED]
D6  RED  [WURTH_LED]
D7  RED  [WURTH_LED]
D8  RED  [WURTH_LED]
E11  FAULT1b  [TP\MMX\2501-2]
E12  ALERTb  [TP\MMX\2501-2]
E13  SDA  [TP\MMX\2501-2]
E14  SCL  [TP\MMX\2501-2]
E15  SHARE_CLK  [TP\MMX\2501-2]
E16  CLKOUT/SYNC  [TP\MMX\2501-2]
E17  FAULT0b  [TP\MMX\2501-2]
E19  RUN0  [TP\MMX\2501-2]
E20  RUN1  [TP\MMX\2501-2]
E21  GND  [TP\MMX\2501-2]
J12  HD2X6-079  [HD2X6-079-MOLEX]
J13  DEMO HEADER (F)  [NPPN072FJFN-RC]
J14  DEMO HEADER (M)  [NPPN072FJFN]
JP3  JP3X1/079\NO\12  [SIP\3P\2MM]
JP4  JP3X1/079\NO\12  [SIP\3P\2MM]
Q3  DMP3130L-7  [SOT23]
Q4  DMP3130L-7  [SOT23]
Q5  DMP3130L-7  [SOT23]
Q6  DMP3130L-7  [SOT23]
Q7  2N7002A  [SOT23]
Q8  2N7002A  [SOT23]
R196  OPT  [0603]
R197  OPT  [0603]
R198  0  [0603]
R199  OPT  [0603]
R200  0  [0603]
R201  OPT  [0603]
R202  0  [0603]
R203  0  [0603]
R204  OPT  [0603]
R205  10  [0603]
R206  10  [0603]
R207  4.99K  [0603]
R208  4.99K  [0603]
R209  OPT  [1206]
R210  OPT  [0603]
R211  OPT  [0603]
R212  OPT  [0603]
R213  OPT  [0603]
R214  2K  [0603]
R215  2K  [0603]
R216  2K  [0603]
R217  2K  [0603]
R218  10K  [0603]
R219  2K  [0603]
R220  15.8k  [0603]
SW1  JP3X1/079\NO\12  [JS202011]
SW2  JP3X1/079\NO\12  [JS202011]
U15  24LC024-I/ST  [TSSOP-8_4.4MM]
XJP6  SHUNT  [NONE]
XJP7  SHUNT  [NONE]
sheet PAGE7
C99  0.1uF  [0603]
C100  0.1uF  [0603]
C101  0.1uF  [0603]
C117  0.1uF  [0603]
C118  0.1uF  [0603]
C119  OPT  [0603]
C120  0.1uF  [0603]
D9  RED  [WURTH_LED]
D10  DIODE SCHOTTKY  [SOD882]
D11  DIODE SCHOTTKY  [SOD882]
D12  DIODE SCHOTTKY  [SOD882]
D13  DIODE SCHOTTKY  [SOD882]
D14  DIODE SCHOTTKY  [SOD882]
D15  DIODE SCHOTTKY  [SOD882]
E8  5V  [TP\MMX\2501-2]
E18  3.3V  [TP\MMX\2501-2]
J22  MOLEX 87831-1420  [MOLEX-87831-1420]
Q9  DMP3130L-7  [SOT23]
R233  2K  [0603]
R259  1  [0603]
R260  1  [0603]
R261  1  [0603]
R264  1  [0603]
R265  10K  [0603]
R266  10K  [0603]
R267  1  [0603]
R270  10K  [0603]
R272  1  [0603]
R273  1  [0603]
U18  NTB0104GU12  [XQFN12]
U19  ADG711BRUZ  [TSSOP16]
U23  SN74AVC4T774  [TSSOP16]
U24  SN74LVC2G34  [SOT23-6]
U25  SC18IS602B  [TSSOP16]
sheet PAGE8
C102  10uF  [0603]
C103  10uF  [0603]
C104  10nF  [0603]
C105  10uF  [0603]
C106  10uF  [0603]
C107  10nF  [0603]
R242  332K  [0603]
R243  3.32K  [0603]
R245  3.32K  [0603]
R246  332K  [0603]
R262  1  [0805]
R263  1  [0805]
U20  LT3080EMS8E-1  [MS8E]
U21  LT3080EMS8E-1  [MS8E]

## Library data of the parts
C1-C6 = CAPR12X5_0: CAP, 270uF 20% 16V OSCON; Component: cap; Manufacturer: SANYO; Part Number: PANASONIC 16SVPC270M; Tolerance: 20%; Type: OS-CON; Volts/Amps/Watts: 16V
C7 C13 C20 C24 C29 C31 C36 C38 C43 C45 C50 C52 C57 C60 C64 C66 = CAP_4: CAP, 0402 0.47uF 10% 16V X5R; Component: cap; Manufacturer: Taiyo Yuden; Manufacturer P/N: LMK212B7475KG-T; Part Number: AVX 0402YD473JAT; Tolerance: 10%; Type: cer 0805 X7R; Vendor: Digikey; Vendor P/N: 587-1442-1-ND; Volts/Amps/Watts: 10V
C8 = CAP_NP: CAP, 0603 4.7uF 10% 10V X5R; Part Number: AVX 0603ZD475KAT2A
C9 C87 COUT43 COUT49 = CAP_NP: CAP, 0603 1uF 20% 25V X5R; Part Number: AVX 06033D105KAT2A
C10 = CAP_NP: CAP, 0603 2.2uF 20% 6.3V X5R; Part Number: TAIYO YUDEN JMK105BJ225MV-T; Volts/Amps/Watts: 50V
C11 = CAP_NP_0: CAP, 0805 2.2uF 10% 16V X7R; Part Number: MURATA GRM21BR71C225KA12L; VOLTAGE: 16V
C12 C14 C23 C25 C30 C32 C37 C39 C44 C46 C51 C53 C58 C59 C65 C67 = CAP_4: CAP, 0603 4.7uF 20% 10V X5R; Component: cap; Manufacturer: Taiyo Yuden; Manufacturer P/N: LMK212B7475KG-T; Part Number: TAIYO YUDEN LMK107BJ475KA-T; Tolerance: 10%; Type: cer 0805 X7R; Vendor: Digikey; Vendor P/N: 587-1442-1-ND; Volts/Amps/Watts: 10V
C15 C26 C33 C40 C47 C54 C61 C68 C121 C122 = CAP_NP: CAP, 0603 220nF 10% 25V X7R; Part Number: TDK C1608X7R1E224K
C16 C27 C34 C41 C48 C55 C62 C69 = CAP_3: CAP, 0402 0.1uF 10% 16V X7R; Manufacturer: TDK; Manufacturer P/N: C1608X7R1H104K; Part Number: AVX 0402YC103KAT2A; Tolerance: 10%; Type: cer 0603 X7R; Vendor: Digikey; Vendor P/N: 445-1314-1-ND; Volts/Amps/Watts: 16V
C17 C28 C35 C42 C49 C56 C63 C70 = CAP_4: CAP, 0402 0.1uF 10% 16V X7R; Component: cap; Manufacturer: Taiyo Yuden; Manufacturer P/N: LMK212B7475KG-T; Part Number: AVX 0402YC103KAT2A; Tolerance: 10%; Type: cer 0805 X7R; Vendor: Digikey; Vendor P/N: 587-1442-1-ND; Volts/Amps/Watts: 16V
C18 C19 = CAP: CAP.,3300pF,X7R,25V,10%,0603; CLASS: DISCRETE; Dielectric Type: X7R; FPLIST: CC0603N,CC0603L,CC0603M; Inventory Qty: 955; Manufacturer: AVX; Manufacturer PN: 06033C332KAT2A; PART_NUMBER: 150-3330; Package Size: 0603; Rated Voltage: 25V; Tolerance: 10%
C21 C22 = CAP_NP: CAP, 0603 330pF 5% 50V C0G; Part Number: MURATA GRM1885C1H331JD01D
CIN1-CIN32 = CAP_NP_0: CAP, 1210 22uF 10% 25V X7R; Part Number: MURATA GRM32ER71E226KE15L; VOLTAGE: 50V; Volts/Amps/Watts: 6.3V
C84 C85 COUT1 COUT2 COUT6 COUT7 COUT10 COUT11 COUT14 COUT15 COUT18 COUT19 COUT22 COUT23 COUT26 COUT27 COUT30 COUT31 COUT40-COUT42 COUT44 COUT47 COUT48 COUT55 COUT56 COUT64 COUT65 = CAP_NP_0: CAP, 1210 100uF 20% 6.3V X5R; Part Number: TDK C3225X5R0J107M; VOLTAGE: 50V; Volts/Amps/Watts: 6.3V
COUT3 COUT8 COUT12 COUT16 COUT20 COUT24 COUT28 COUT32 = t510x337k010as: CAP, 7343 470uF 20% 6.3V TANT. POLYMER; 1st Part Field: 2.5V; 3rd Part Field: POSCAP; Part Number: PANASONIC 6TCF470MAH
COUT4 COUT9 COUT13 COUT17 COUT21 COUT25 COUT29 COUT33 COUT50-COUT54 COUT57-COUT59 COUT62 = t510x337k010as: CAP, 7343 470uF 20% 2.5V TANT. POLYMER; 1st Part Field: 2.5V; 3rd Part Field: POSCAP; Part Number: PANASONIC ETPF470M5H
E1-E25 = E_0: TURRET; Part Number: MILL MAX 2501-2-00-80-00-00-07-0
J1 = BANANA_SMALL_0: STUD, TEST PIN; Component: conn; Label: VIN; Part Number: PEM KFH-032-10
J2 J4 J6 = BANANA_SMALL_0: STUD, TEST PIN; Component: conn; Label: GND; Part Number: PEM KFH-032-10
J3 = BANANA_SMALL_0: STUD, TEST PIN; Component: conn; Label: VOUT0; Part Number: PEM KFH-032-10
L1-L8 = INDUCTOR_IRON: IND, 0.25uH; Part Number: WURTH ELEKTRONIK 744301025
P1-P8 = PAD_2: Component: tp; Label: <Label>; Vendor: Digikey; Vendor P/N: 1593-2K-ND
R1 R7 R8 R11 R12 R22 R23 R25 R33-R36 R46 R50 R55 R60-R62 R64 R66 R68 R69 R73 R75 R77 R78 R81-R83 R87 R90 R92 R93 R96 R97 R99 R103 R105-R107 R110 R112 R113 R118-R120 R122 R124 R126 R127 R132-R135 R138 R139 = RES0603_9: RES, 0402 2 OHMS 1% 1/16W; Manufacturer: Panasonic; Part Number: VISHAY CRCW04022R00FNEA; Vendor: Digikey; Vendor P/N: P100HCT-ND; Volts/Amps/Watts: 0.1W
R2 R4-R6 R21 R26 R27 R29 R32 R43 R56-R59 R67 R70-R72 R74 R80 R84-R86 R88 R95 R100-R102 R104 R111 R114-R117 R125 R128-R131 R140 R276 R279 R281 R283 R286 R288 = RES0603_9: RES, 0402 0 OHM JUMPER; Manufacturer: Panasonic; Part Number: VISHAY CRCW04020000Z0EA; Vendor: Digikey; Vendor P/N: P100HCT-ND; Volts/Amps/Watts: 0.1W
R3 = RES0603_0: RES, 0603 1 OHMS 1% 1/10W; Component: res; Label: <label>; Manufacturer: Panasonic; Manufacturer P/N: ERJ-3EKF5901V; Part Number: VISHAY CRCW06031R00FNEA; Tolerance: 1%; Vendor: Digikey; Vendor P/N: P5.90KHCT-ND; Volts/Amps/Watts: 0.1W
R9 R10 R18 = RES0603_0: RES, 0603 1K OHMS 5% 0.1W; Manufacturer: ROHM; Manufacturer P/N: MCR03EZPFX1002; Part Number: VISHAY CRCW06031K00JNEA; Vendor: Digikey; Vendor P/N: RHM10.0KHCT-ND; Volts/Amps/Watts: 0.1W
R15 R17 R244 = RES0603_0: RES, 0603 10K OHMS 5% 0.1W; Manufacturer: ROHM; Manufacturer P/N: MCR03EZPFX1002; Part Number: VISHAY CRCW060310K0JNEA; Vendor: Digikey; Vendor P/N: RHM10.0KHCT-ND; Volts/Amps/Watts: 0.1W
R16 = RES0603_0: RES, 0603 5k OHMS 5% 0.1W; Manufacturer: ROHM; Manufacturer P/N: MCR03EZPFX1002; Part Number: VISHAY CRCW06035K00JNED; Vendor: Digikey; Vendor P/N: RHM10.0KHCT-ND; Volts/Amps/Watts: 0.1W
R28 R30 R37 = RES0603_0: RES, 0603 OPTION; Manufacturer: Rohm; Manufacturer P/N: RHM0.0GCT-ND; Part Number: OPTION; Tolerance: 5%; Vendor: Digikey; Vendor P/N: RHM0.0GCT-ND; Volts/Amps/Watts: 0.1W
R38 = RES0603_0: RES, 0603 OPTION; Manufacturer: Panasonic; Manufacturer P/N: ERJ-3EKF2002V; Part Number: OPTION; Tolerance: 5%; Vendor: Digikey; Vendor P/N: P20.0KHCT-ND; Volts/Amps/Watts: 0.1W
R39-R42 = RES0603_0: RES, 0603 OPTION; Manufacturer: Panasonic; Manufacturer P/N: ERJ-3EKF2002V; Part Number: OPTION; Vendor: Digikey; Vendor P/N: P20.0KHCT-ND; Volts/Amps/Watts: 0.1W
R44 R47 R51 R52 R290 = RES0603_0: RES, 0603 OPTION; Manufacturer: ROHM; Manufacturer P/N: MCR03EZPFX1002; Part Number: OPTION; Vendor: Digikey; Vendor P/N: RHM10.0KHCT-ND; Volts/Amps/Watts: 0.1W
R48 R53 R54 R274 R275 R277 R278 R280 R282 R284 R285 R287 R289 R291 = RES0603_0: RES, 0603 10K OHMS 5% .01W; Manufacturer: Panasonic; Manufacturer P/N: ERJ-3EKF2002V; Part Number: VISHAY CRCW060310K0JNEA; Vendor: Digikey; Vendor P/N: P20.0KHCT-ND; Volts/Amps/Watts: 0.1W
R49 = R_1: RES, 0603 0 OHMS JUMPER; %: 0.1%; Part Number: VISHAY CRCW06030000Z0EA
R89 R234 R235 = RES0603_0: RES, 0603 10 OHMS 1% 0.1W; Manufacturer: Yageo; Manufacturer P/N: RC0603JR-070RL; Part Number: VISHAY CRCW060310R0FKEA; Tolerance: 1%; Vendor: Digikey; Vendor P/N: 311-0.0GRCT-ND; Volts/Amps/Watts: 0.1W
R202 R242 R243 R245 R246 R259-R270 R272 R273 R292 = RES0603_0: RES, 0603 0 OHMS JUMPER; Manufacturer: Rohm; Manufacturer P/N: RHM0.0GCT-ND; Part Number: VISHAY CRCW06030000Z0EA; Tolerance: 5%; Vendor: Digikey; Vendor P/N: RHM0.0GCT-ND; Volts/Amps/Watts: 0.1W
U1 = LTC3880-M0001_6: IC, DUAL OUTPUT STEP-DOWN CONTROLLER; Component: IC; Manufacturer: LTC; Manufacturer P/N: LTC3880_M0001; Part Number: LINEAR TECH. LTC3884EUK; Part Type: LTC3884EUK
U2-U9 = LTC_2
J5 = BANANA_SMALL_0: STUD, TEST PIN; Component: conn; Label: VOUT1; Part Number: PEM KFH-032-10
R98 = RES0603_0: RES, 0603 10 OHMS 1% 1/10W; Manufacturer: Yageo; Manufacturer P/N: RC0603JR-070RL; Part Number: VISHAY CRCW060310R0FKEA; Tolerance: 1%; Vendor: Digikey; Vendor P/N: 311-0.0GRCT-ND; Volts/Amps/Watts: 0.1W
C86 C90 = CAP_NP: CAP, 0603 100nF 20% 16V X7R; Part Number: AVX 0603YC104MAT2A
C88 = CAP_NP: CAP, 0603 150pF 5% 50V NPO; Part Number: AVX 06035A151JAT2A
C89 = CAP_NP_1: CAP, 0603 1uF 20% 25V X5R; Part Number: AVX 06033D105KAT2A
C108 = CAP_NP: CAP, 0805 2.2uF 20% 50V Y5V; Part Number: TDK C2012Y5V1H225Z; Voltage: 16V
C110 C113 = CAP_NP: CAP, 0805 1uF 10% 50V X7R; Part Number: MURATA GRM21BR71H105KA12L; TOL: X7R
C111 = CAP_NP: CAP, 0603 4.7uF 10% 10V X5R; Part Number: TDK C1608X5R1A475K-T; TOL: X5R
C112 = CAP_NP_0: CAP, 0603 0.1uF 10% 50V X7R; Part Number: AVX 06035C104KAT2A; Tol: X7R
C114 = LMK107BJ105KA: CAP, 0603 5.6pF +/-.25pF 50V NPO; Part Number: AVX 06035A5R6CAT2A; Tol: NPO
C115 = CAP_NP_0: CAP, 0603 OPTION; Part Number: OPTION
C116 = CAP_NP_0: CAP, 0603 100pF 10% 50V X7R; Part Number: AVX 06035C101KAT2A; Tol: X7R
CIN33 CIN34 = CAP_NP: CAP, 1210 10uF 20% 50V X5R; CASE: 1210; Part Number: TAIYO YUDEN UMK325BJ106MM-T; Voltage: 16V
COUT38 COUT45 COUT46 = t510x337k010as: CAP, 7343 470uF 20% 2.5V TANT POLYMER OPTION; 1st Part Field: 2.5V; 3rd Part Field: POSCAP; Part Number: PANASONIC ETPF470M5H OPTION
COUT39 COUT60 COUT61 COUT63 = CAP_P_ALT: CAP.,470uF,ALUM. ELECT.,2.5V,20%,7343; CLASS: DISCRETE; Dielectric Type: ALUM. ELECT.; FPLIST: CAPMP7343N,CAPMP7343L,CAPMP7343M; Inventory Qty: 400; Manufacturer: PANASONIC; Manufacturer PN: EEFGX0E471R; PART_NUMBER: 150-2304; Package Size: 7343; Rated Voltage: 2.5V; Tolerance: 20%
COUT66 = CAP_NP: CAP, 1210 4.7uF 20% 16V X7R; Case: 1210; FIELD1: 0805; Part Number: TAIYO YUDEN EMK325BJ475MN-T; Tolerance: X5R; Voltage: 16V
COUT67 = CAP_NP: CAP, 1210 10uF 20% 16V X5R; Case: 1210; FIELD1: 0805; Part Number: TDK C3225X7R1C106M; Tolerance: X5R; Voltage: 16V
D1 = DIODE_SCHOTTKY: DIODE, OPTION; Part Number: OPTION
J8 = BNC5-SCH_14: CONN, BNC, 5 PINS; Part Number: CONNEX 112404
J9 = BNC5-SCH_15: CONN, BNC, 5 PINS; Part Number: CONNEX 112404; Pin Numbers Visible: <Pin Numbers Visible>
J10 = BNC5-SCH_16: CONN, BNC, 5 PINS; Part Number: CONNEX 112404
JP1 = Samtec_TMM-103-02-L-S: HEADER, 2mm, 3PIN; 11th Part Field: OFF; 12th Part Field: RUN; 9th Part Field: ON; Part Number: SAMTEC TMM-103-02-L-S
JP2-JP4 = JP3X1_079_NO_12_1_v2: HEADER, SINGLE ROW 3PIN; Part Number: SAMTEC TMM-103-02-L-S
L9 = INDUCTOR: IND, 4.7uH; Part Number: COILCRAFT XAL5030-472MEB
Q1 Q2 = 2N7002_13: XSTR, MOSFET, N-CHANNEL 30V; Part Number: VISHAY SUD50N04-8M8P
R162 = RES0603_0: RES, 2010 0 OHM JUMPER; Label: 2; Part Number: VISHAY CRCW20100000Z0EF; Part Type: RES0603; Tolerance: 1%; Vendor: Digikey; Vendor P/N: RHM0.0GCT-ND; Volts/Amps/Watts: 0.1W
R163 = RES0603_0: RES, 2010 0 OHM JUMPER; Label: OPT 0; Manufacturer: Rohm; Manufacturer P/N: RHM0.0GCT-ND; Part Number: VISHAY CRCW20100000Z0EF; Tolerance: 5%; Vendor: Digikey; Vendor P/N: RHM0.0GCT-ND; Volts/Amps/Watts: 0.1W
R164 = RES0603_0: RES, 0603 2 OHMS 5% 1/10W; Manufacturer: ROHM; Manufacturer P/N: MCR03EZPFX4991; Part Number: VISHAY CRCW06032R00JNED; Vendor: Digikey; Vendor P/N: RHM4.99KHCT-ND; Volts/Amps/Watts: 0.1w
R165 = RES0603_0: RES, 0603 3.3 OHMS 1% 1/10W; Manufacturer: ROHM; Manufacturer P/N: MCR03EZPFX4991; Part Number: VISHAY CRCW06033R30FNEA; Tolerance: 1%; Vendor: Digikey
R166 = RES0603_0: RES, 0603 0 OHMS JUMPER; Component: res; Label: <label>; Manufacturer: Panasonic; Manufacturer P/N: ERJ-3EKF5901V; Part Number: VISHAY CRCW06030000Z0EA; Tolerance: 1%; Vendor: Digikey; Vendor P/N: P5.90KHCT-ND; Volts/Amps/Watts: 0.1W
R167 = RES0603_0: RES, 0603 154k OHMS 1% 1/10W; Component: res; Label: <label>; Manufacturer: Panasonic; Manufacturer P/N: ERJ-3EKF5901V; Part Number: VISHAY CRCW0603154KFKEA; Tolerance: 1%; Vendor: Digikey; Vendor P/N: P5.90KHCT-ND; Volts/Amps/Watts: 0.1W
R168 = RES0603_0: RES, 0603 1M OHMS 5% 1/10W; Label: OPT 0; Manufacturer: Rohm; Manufacturer P/N: RHM0.0GCT-ND; Part Number: VISHAY CRCW06031M00JNEA; Vendor: Digikey
R169 R170 = RES0603_0: RES, 0603 20K OHMS 5% 1/10W; Manufacturer: Panasonic; Manufacturer P/N: ERJ-3EKF2002V; Part Number: VISHAY CRCW060320K0JNEA; Vendor: Digikey; Vendor P/N: P20.0KHCT-ND; Volts/Amps/Watts: 0.1W
R171 = RES0603_0: RES, 0603 681K OHMS 1% 1/10W; Manufacturer: ROHM; Manufacturer P/N: MCR03EZPFX4991; Part Number: VISHAY CRCW0603681KFEA; Tolerance: 1%
R172 = RES0603_0: RES, 0603 10K OHMS 5% 1/10W; Manufacturer: Panasonic; Manufacturer P/N: ERJ-3EKF2002V; Part Number: VISHAY CRCW060310K0JNEA; Vendor: Digikey
R173 = RES0603_0: RES, 0603 301 OHMS 1% 1/10W; Manufacturer: ROHM; Manufacturer P/N: MCR03EZPFX4991; Part Number: VISHAY CRCW0603301RFKEA; Vendor: Digikey; Vendor P/N: RHM4.99KHCT-ND; Volts/Amps/Watts: 0.1w
R174 = RES0603_0: RES, 0603 82.5 OHMS 5% 1/10W; Manufacturer: ROHM; Manufacturer P/N: MCR03EZPFX4991; Part Number: VISHAY CRCW060382R5FKEA; Tolerance: 1%; Vendor: Digikey
R175 = POT: RES, VARIABLE 5K; Part Number: BOURNS 3386P-1-502-LF
R176 R185 = RES0603_5: RES, 2512 OPTION; Label: 1W; Manufacturer: VISHAY; Manufacturer P/N: CRCW251230R0JNEG; Part Number: OPTION; Tolerance: 5%
R177 = RES0603_5: RES, 2512 0.01 OHMS 1% 1W; Label: 1W; Manufacturer: VISHAY; Manufacturer P/N: CRCW251230R0JNEG; Part Number: VISHAY WSL2512R0100FEA; Tolerance: 5%
R178 = RES0603_0: RES, 0603 1k OHMS 1% 1/10W; Manufacturer: ROHM; Manufacturer P/N: MCR03EZPFX4991; Part Number: VISHAY CRCW06031K00FKEA; Vendor: Digikey; Vendor P/N: RHM4.99KHCT-ND; Volts/Amps/Watts: 0.1w
R179-R182 R187 R188 R191 = RES0603_0: RES, 0603 0 OHMS JUMPER; Label: <label>; Manufacturer: Panasonic; Manufacturer P/N: ERJ-3EKF5901V; Part Number: VISHAY CRCW06030000Z0EA; Vendor: Digikey; Vendor P/N: P20.0KHCT-ND; Volts/Amps/Watts: 0.1W
R183 R184 R189 R190 R192-R195 = RES0603_0: RES, 2010 0 OHM JUMPER; Label: 2; Part Number: VISHAY WSL201000000ZEA9; Vendor: Digikey; Vendor P/N: RHM0.0GCT-ND; Volts/Amps/Watts: 0.1W
R186 = RES0603_6: RES, 2512 OPTION; Label: 1W; Part Number: OPTION; Tolerance: 5%
R250 = RESISTOR: RES, 0603 2 OHMS 5% 1/10W; Part Number: VISHAY CRCW06032R00FNEA; Tolerance: OPT
R251 R257 R258 = RESISTOR: RES, 0603 100K OHM 5% 1/10W; Part Number: VISHAY CRCW0603100KJNEA; Tol: 5%
R252 = RESISTOR: RES, 0603 60.4k OHMS 1% 1/10W; Part Number: VISHAY CRCW060360K4FKED; Tolerance: 1%
R253 = RESISTOR: RES, 0603 619k OHM 1% 1/10W; Part Number: VISHAY CRCW0603619KFKEA; Tol: 1%
R255 = RESISTOR: RES, 0603 200k OHMS 1% 1/10W; Part Number: VISHAY CRCW0603200KFKEA; Tolerance: 1%
R256 = R: RES, 0603 84.5k OHMS 1% 1/10W; 5%: 1%; Part Number: VISHAY CRCW060384K5FKEA; Tol: 1%
U13 = LT1129CS8-3_0.3: IC, LTC6992IS6-1; Part Number: LINEAR TECH. LTC6992IS6-1
U14 = LT1129CS8-3_1.3: IC, SINGLE OP AMP; Part Number: LINEAR TECH. LT1803IS5
U22 = LTC3634EUFD-B_7: IC, HIGH EFFICIENCY LOW QUIESCENT CURRENT STEP-DOWN CONVERTER; Part Number: LINEAR TECH LTC3646EDE / LTC3646EDE-1
XJP2 XJP6 XJP7 = SHUNT: Part Number: SAMTEC 2SN-BK-G
XJP5 = Samtec_2SN-BK-G: SHUNT, 2mm; Part Number: SAMTEC 2SN-BK-G
C91 C92 = CAP_NP: CAP, 0603 10nF 10% 25V X7R; Part Number: AVX 06033C103KAT2A
D2 D3 = DIODE_SCHOTTKY_9: DIODE, SCHOTTKY 30V, 100mA OPTION; Part Number: CENTRAL SEMI CMDSH-3-TR OPTION
D4-D9 = DIODE-LED_WURTH: Label: GREEN
J12 = HD2X6-079-PMBUS_2: HEADER, 12PIN 2mm STR DL; Label: DC1427A HEADER; Manufacturer: MOLEX; Manufacturer P/N: 87831-1220; Part Number: FCI 98414-G06-12ULF; Type: header 12POS 2MM VERT; Vendor: Digikey; Vendor P/N: WM18561-ND
J13 = PMBUS_CONNECTOR20_3: CONN, SOCKET 14PIN  DUAL ROW R/A; Component: con; Manufacturer: Mill Max; Manufacturer P/N: 803-93-020-20-001; Part Number: SULLINSINC. NPPN072FJFN-RC; Part Type: HDR2X10RA; Type: conn  RA 20 dual row; Vendor: LTC; Vendor P/N: 803-93-020-20-001
J14 = PMBUS_HEADER20_3: HEADER, 14PIN DUAL ROW R/A; Component: con; Manufacturer: Mill Max; Manufacturer P/N: 802-40-020-20-0001; Part Number: MOLEX 87760-1416; Part Type: HDR_2X10_RA_REV; Type: header RA 20 dual row; Vendor: LTC; Vendor P/N: 802-40-020-20-001
Q3-Q6 Q9 = P-MOSFET: XSTR, P-CHANNEL DMOS FET; Part Number: DIODES INC. DMP3130L-7
Q7 = TRANSISTOR_0: XSTR, N-CHANNEL DMOS FET; Part Number: FAIRCHILD 2N7002A
Q8 = TRANSISTOR_1: XSTR, N-CHANNEL DMOS FET; Part Number: FAIRCHILD 2N7002A
R196 R197 R199 R201 R203 R204 R210 R212 R213 = RES0603_0: RES, 0603 OPTION; Label: OPT 0; Manufacturer: Rohm; Manufacturer P/N: RHM0.0GCT-ND; Part Number: OPTION; Tolerance: 5%; Vendor: Digikey; Vendor P/N: RHM0.0GCT-ND; Volts/Amps/Watts: 0.1W
R198 R200 = RES0603_0: RES, 0603 0 OHMS JUMPER; Label: OPT 0; Manufacturer: Rohm; Manufacturer P/N: RHM0.0GCT-ND; Part Number: VISHAY CRCW06030000Z0EA; Tolerance: 5%; Vendor: Digikey; Vendor P/N: RHM0.0GCT-ND; Volts/Amps/Watts: 0.1W
R205 R206 = RES0603_1: RES, 0603 10 OHMS 5% 1/10W; Manufacturer: Rohm; Manufacturer P/N: RHM0.0GCT-ND; Part Number: VISHAY CRCW060310R0JNEA; Tolerance: 5%; Vendor: Digikey; Vendor P/N: RHM0.0GCT-ND; Volts/Amps/Watts: 0.1W
R207 R208 = RES0603_0: RES, 0603 4.99K OHMS 1% 1/10W; Manufacturer: ROHM; Manufacturer P/N: MCR03EZPFX4991; Part Number: VISHAY CRCW06034K99FKEA; Vendor: Digikey; Vendor P/N: RHM4.99KHCT-ND; Volts/Amps/Watts: 0.1w
R209 R211 = RES0603_3: RES, 0603 OPTION; Label: OPT 0; Manufacturer: Rohm; Manufacturer P/N: RHM0.0GCT-ND; Part Number: OPTION; Tolerance: 5%; Vendor: Digikey; Vendor P/N: RHM0.0GCT-ND; Volts/Amps/Watts: 0.1W
R214 R215 R219 R233 = RES0603_0: RES, 0603 127 OHMS 1% 1/10W; Label: OPT 0; Manufacturer: Rohm; Manufacturer P/N: RHM0.0GCT-ND; Part Number: VISHAY CRCW0603127RFKEA; Tolerance: 5%; Vendor: Digikey; Vendor P/N: RHM0.0GCT-ND; Volts/Amps/Watts: 0.1W
R216 R217 = RES0603_0: RES, 0603 200 OHMS 5% 1/10W; Label: OPT 0; Manufacturer: Rohm; Manufacturer P/N: RHM0.0GCT-ND; Part Number: VISHAY CRCW0603200RJNEA; Tolerance: 5%; Vendor: Digikey; Vendor P/N: RHM0.0GCT-ND; Volts/Amps/Watts: 0.1W
R218 = RES0603_11: RES, 0603 10K OHMS 5% 1/10W; Part Number: VISHAY CRCW060310K0JNEA
R220 = RES0603_11: RES, 0603 15.8K OHMS 1% 1/10W; Part Number: VISHAY CRCW060315K8FKEA
SW1 = JP3X1_079_NO_12_1: SWITCH, SUBMINATURE SLIDE; Part Number: C&K JS202011CQN
SW2 = JP3X1_079_NO_12_0: SWITCH, SUBMINATURE SLIDE; Part Number: C&K JS202011CQN
U15 = 24LC025-I_SN: IC, 2K EEPROM; Part Number: MICROCHIP 24LC024-I/ST
C99-C101 C117-C120 = CAP_NP_0: CAP, 0603 0.1uF 10% 25V X5R; Part Number: AVX 06033C104KAT2A; VOLTAGE: 50V
D10-D15 = DIODE_SCHOTTKY_0: DIODE, ULTRA LOW  SCHOTTKY RECTIEIER; Part Number: NXP SEMI. PMEG2005AEL,315; VOLTAGE: 0.5A
J22 = MOLEX_87831-1420: HD2X7-079-MOLEX; Component: con; Manufacturer: MOLEX; Vendor P/N: HD2X7-079-MOLEX
U18 = NTB0104GU12_0
U19 = ADG711BRUZ_0
U23 = SN74AVC4T774
U24 = SN74LVC2G34: DES: IC
U25 = SC18IS602B_4: DES: IC
C102-C107 = CAP_NP_0: CAP, 0603 0.1uF 10% 25V X5R; Part Number: AVX 06033C104KAT2A; VOLTAGE: 10V
U20 U21 = LT3080EMS8E-1_1

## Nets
3V3: D13.1(CATHODE) D14.1(CATHODE) D15.1(CATHODE) E18.1(A) Q3.2(S) Q4.3(D) Q5.2(S) Q6.2(S) Q9.2(S) R201.1 R216.1 R217.1 R260.1 R264.1 R267.1 R272.1 R273.1
3V3_1: D13.2(ANODE) J12.5(LGKPWR)
3V3_2: C105.1 D14.2(ANODE) R245.1 U21.1(OUT) U21.2(OUT) U21.3(OUT) U21.9(OUT)
3V3_3: C103.1 D15.2(ANODE) R243.1 U20.1(OUT) U20.2(OUT) U20.3(OUT) U20.9(OUT)
5V: D10.1(CATHODE) D11.1(CATHODE) D12.1(CATHODE) E8.1(A) R259.1 R261.1
5V_1: C90.1 D10.2(ANODE) J12.1(AUXP) J13.8(AUXP) J14.8(AUXP) R207.1 R208.1 U15.8(VCC)
5V_2: D11.2(ANODE) J22.10(+5V(EEVCC)) U21.5(Vc)
GND_POWER: C1.2 C2.2 C3.2 C4.2 C5.2 C6.2 C8.1 C9.1 C10.1 C11.1 C12.2 C14.1 C16.2 C17.2 C18.1 C19.1 C21.1 C22.1 C23.2 C25.1 C27.2 C28.2 C30.2 C32.1 C34.2 C35.2 C37.2 C39.1 C41.2 C42.2 C44.2 C46.1 C48.2 C49.2 C51.2 C53.1 C55.2 C56.2 C58.2 C59.1 C62.2 C63.2 C65.2 C67.1 C69.2 C70.2 C84.2 C85.2 C86.2 C87.1 C89.1 C90.2 C91.2 C92.2 C99.2 C100.2 C101.2 C102.2 C103.2 C104.2 C105.2 C106.2 C107.2 C108.2 C110.2 C111.1 C113.2 C115.2 C116.2 C117.2 C118.2 C119.2 C120.2 CIN1.2 CIN2.2 CIN3.2 CIN4.2 CIN5.2 CIN6.2 CIN7.2 CIN8.2 CIN9.2 CIN10.2 CIN11.2 CIN12.2 CIN13.2 CIN14.2 CIN15.2 CIN16.2 CIN17.2 CIN18.2 CIN19.2 CIN20.2 CIN21.2 CIN22.2 CIN23.2 CIN24.2 CIN25.2 CIN26.2 CIN27.2 CIN28.2 CIN29.2 CIN30.2 CIN31.2 CIN32.2 CIN33.2 CIN34.2 COUT1.2 COUT2.2 COUT3.2 COUT4.2 COUT6.2 COUT7.2 COUT8.2 COUT9.2 COUT10.2 COUT11.2 COUT12.2 COUT13.2 COUT14.2 COUT15.2 COUT16.2 COUT17.2 COUT18.2 COUT19.2 COUT20.2 COUT21.2 COUT22.2 COUT23.2 COUT24.2 COUT25.2 COUT26.2 COUT27.2 COUT28.2 COUT29.2 COUT30.2 COUT31.2 COUT32.2 COUT33.2 COUT38.2 COUT39.2 COUT40.2 COUT41.2 COUT42.2 COUT43.1 COUT44.2 COUT45.2 COUT46.2 COUT47.2 COUT48.2 COUT49.1 COUT50.2 COUT51.2 COUT52.2 COUT53.2 COUT54.2 COUT55.2 COUT56.2 COUT57.2 COUT58.2 COUT59.2 COUT60.2 COUT61.2 COUT62.2 COUT63.2 COUT64.2 COUT65.2 COUT66.2 COUT67.2 E2.1(A) E10.1(A) E21.1(A) J2.1(TP) J4.1(TP) J6.1(TP) J8.2 J8.3(GND_POWER) J8.4(GND_POWER) J8.5(GND_POWER) J9.2 J9.3(GND_POWER) J9.4(GND_POWER) J9.5(GND_POWER) J10.2 J10.3(GND_POWER) J10.4(GND_POWER) J10.5(GND_POWER) J12.3(GND) J12.10(GND) J13.11(GND) J13.12(GND) J14.11(GND) J14.12(GND) J22.3(GND) J22.8(GND) J22.12(GND) J22.13(GND) JP1.3 JP3.3 Q7.2(S) Q8.2(S) R21.1 R23.2 R37.1 R38.1 R39.1 R40.1 R41.1 R42.1 R43.1 R44.1 R46.2 R47.1 R67.1 R68.2 R80.1 R82.2 R95.1 R97.2 R98.1 R111.1 R112.2 R125.1 R126.2 R139.2 R140.1 R170.1 R171.2 R172.1 R175.1(A) R175.2(WIPER) R176.1 R177.1 R178.2 R185.1 R186.1 R214.2 R215.2 R219.2 R220.2 R233.2 R235.1 R242.2 R243.2 R245.2 R246.2 R252.1 R256.1 R257.2 R269.2 R270.2 R278.2 R285.2 R290.1 SW1.3 SW2.3 U1.53(GND) U2.5(PGND) U2.7(PGND) U2.8(PGND) U2.9(PGND) U2.20(PGND) U2.21(PGND) U2.22(PGND) U2.23(PGND) U2.24(PGND) U2.40(PGND) U3.5(PGND) U3.7(PGND) U3.8(PGND) U3.9(PGND) U3.20(PGND) U3.21(PGND) U3.22(PGND) U3.23(PGND) U3.24(PGND) U3.40(PGND) U4.5(PGND) U4.7(PGND) U4.8(PGND) U4.9(PGND) U4.20(PGND) U4.21(PGND) U4.22(PGND) U4.23(PGND) U4.24(PGND) U4.40(PGND) U5.5(PGND) U5.7(PGND) U5.8(PGND) U5.9(PGND) U5.20(PGND) U5.21(PGND) U5.22(PGND) U5.23(PGND) U5.24(PGND) U5.40(PGND) U6.5(PGND) U6.7(PGND) U6.8(PGND) U6.9(PGND) U6.20(PGND) U6.21(PGND) U6.22(PGND) U6.23(PGND) U6.24(PGND) U6.40(PGND) U7.5(PGND) U7.7(PGND) U7.8(PGND) U7.9(PGND) U7.20(PGND) U7.21(PGND) U7.22(PGND) U7.23(PGND) U7.24(PGND) U7.40(PGND) U8.5(PGND) U8.7(PGND) U8.8(PGND) U8.9(PGND) U8.20(PGND) U8.21(PGND) U8.22(PGND) U8.23(PGND) U8.24(PGND) U8.40(PGND) U9.5(PGND) U9.7(PGND) U9.8(PGND) U9.9(PGND) U9.20(PGND) U9.21(PGND) U9.22(PGND) U9.23(PGND) U9.24(PGND) U9.40(PGND) U13.2(GND) U14.2(V-) U15.1(A0) U15.2(A1) U15.3(A2) U15.4(VSS) U15.7(WP) U18.6(GND) U19.5(GND) U22.1(SGND) U22.12(EXTVCC) U22.15(PGND) U23.2(DIR2) U23.10(GND) U24.2(GND) U25.4(VSS) U25.14(A0) U25.15(A1) U25.16(A2)
VCCA: J22.2(VCCA(5/3.3V)) R263.2
VDD25: C9.2 U1.28(VDD25)
VDD33: C10.2 Q4.2(S) R9.1 R10.1 R15.2 R16.2 R17.2 R18.2 R48.2 R49.2 R51.1 R52.1 R53.2 R54.1 R244.2 U1.30(VDD33)
VIN: C1.1 C2.1 C3.1 C4.1 C5.1 C6.1 CIN1.1 CIN2.1 CIN3.1 CIN4.1 CIN5.1 CIN6.1 CIN7.1 CIN8.1 CIN9.1 CIN10.1 CIN11.1 CIN12.1 CIN13.1 CIN14.1 CIN15.1 CIN16.1 CIN17.1 CIN18.1 CIN19.1 CIN20.1 CIN21.1 CIN22.1 CIN23.1 CIN24.1 CIN25.1 CIN26.1 CIN27.1 CIN28.1 CIN29.1 CIN30.1 CIN31.1 CIN32.1 E1.1(A) J1.1(TP) R3.1 R209.1 R218.1 R258.2 U2.25(VIN) U2.26(VIN) U2.27(VIN) U2.28(VIN) U2.29(VIN) U2.30(VIN) U3.25(VIN) U3.26(VIN) U3.27(VIN) U3.28(VIN) U3.29(VIN) U3.30(VIN) U4.25(VIN) U4.26(VIN) U4.27(VIN) U4.28(VIN) U4.29(VIN) U4.30(VIN) U5.25(VIN) U5.26(VIN) U5.27(VIN) U5.28(VIN) U5.29(VIN) U5.30(VIN) U6.25(VIN) U6.26(VIN) U6.27(VIN) U6.28(VIN) U6.29(VIN) U6.30(VIN) U7.25(VIN) U7.26(VIN) U7.27(VIN) U7.28(VIN) U7.29(VIN) U7.30(VIN) U8.25(VIN) U8.26(VIN) U8.27(VIN) U8.28(VIN) U8.29(VIN) U8.30(VIN) U9.25(VIN) U9.26(VIN) U9.27(VIN) U9.28(VIN) U9.29(VIN) U9.30(VIN)
ALERTb: E12.1(A) J12.6(ALERTB) J13.3(ALERTB) J14.3(ALERTB) Q3.1(G) R17.1 U1.17(ALERTb) U19.10(D3)
ASEL0: R37.2 U1.23(ASEL0)
ASEL1: R38.2 U1.24(ASEL1)
EESCL: J12.11(AUXSCL) R207.2 U15.6(SCL)
EESDA: J12.12(AUXSDA) R208.2 U15.5(SDA)
FAULT0b: D3.2(ANODE) E17.1(A) Q5.1(G) R48.1 R187.1 R198.2 R199.2 U1.18(FAULT0b)
FAULT1b: D2.2(ANODE) E11.1(A) Q6.1(G) R49.1 R187.2 R196.2 R197.2 U1.19(FAULT1b)
INTVCC: C8.2 E22.1(A) U1.31(INTVCC)
INTVCC1: C111.2 D1.2(ANODE) R251.2 U22.11(INTVCC)
IREF: C15.2 C16.1 C26.2 C27.1 C33.2 C34.1 C40.2 C41.1 C47.2 C48.1 C54.2 C55.1 C61.2 C62.1 C68.2 C69.1 R11.1 R12.1 R35.1 R36.1 R62.1 R64.1 R77.1 R78.1 R92.1 R93.1 R106.1 R107.1 R120.1 R122.1 R134.1 R135.1 U1.33(IREF)
ISENSE1: C45.2 C47.1 R90.1 R92.2 U1.43(ISENSE1)
ISENSE2: C24.2 C26.1 R34.1 R35.2 U1.3(ISENSE2)
ISENSE3: C31.2 C33.1 R61.1 R62.2 U1.52(ISENSE3)
ISENSE4: C38.2 C40.1 R75.1 R77.2 U1.51(ISENSE4)
ISENSE5: C52.2 C54.1 R105.1 R106.2 U1.48(ISENSE5)
ISENSE6: C60.2 C61.1 R119.1 R120.2 U1.47(ISENSE6)
ISENSE7: C66.2 C68.1 R133.1 R134.2 U1.44(ISENSE7)
ITH0: C21.2 R179.1 U1.9(ITH0)
ITH1: C22.2 R179.2 U1.38(ITH1)
ITHR0: C18.2 R191.1 U1.10(ITH_R0)
ITHR1: C19.2 R191.2 U1.37(ITH_R1)
OE: R265.1 U18.12(OE) U23.9(\\~{OE}\) U24.6(1Y)
PGOOD0/CLKOUT: JP3.1 JP4.3 R53.1 R188.1 R276.1 R282.2
PGOOD1: Q8.1(G) R54.2 R188.2 R283.2 R289.2
PWM1: R83.1 U1.42(PWM1)
PWM2: R25.1 U1.2(PWM2)
PWM3: R55.1 U1.1(PWM3)
PWM4: R69.1 U1.50(PWM4)
PWM5: R99.1 U1.49(PWM5)
PWM6: R113.1 U1.46(PWM6)
PWM7: R127.1 U1.45(PWM7)
RUN0: D3.1(CATHODE) E19.1(A) R4.2 R15.1 R26.2 R56.2 R70.2 R181.1 R197.1 R200.2 R206.2 R210.2 SW2.1 SW2.2 U1.20(RUN0)
RUN1: D2.1(CATHODE) E20.1(A) R84.2 R100.2 R114.2 R128.2 R181.2 R199.1 R204.2 R205.2 R212.2 R244.1 SW1.1 SW1.2 U1.21(RUN1)
SCK: E23.1(A) R281.2 U18.2(A1) U23.14(B1)
SCL: E14.1(A) J12.4(SCL) J13.6(SCL) J14.6(SCL) R18.1 U1.15(SCL) U19.15(D2) U25.8(SCL)
SCSb: E7.1(A) R52.2 R286.2 U18.4(A3) U23.12(B3)
SDA: E13.1(A) J12.2(SDA) J13.4(SDA) J14.4(SDA) R9.2 U1.16(SDA) U19.2(D1) U25.7(SDA)
SDI: E25.1(A) R279.2 U18.5(A4) U23.11(B4) U23.13(B2)
SERRb: E24.1(A) Q9.1(G) R51.2 R288.2 U24.3(2A)
SHARE_CLK: E15.1(A) R16.1 R202.1 U1.29(SHARE_CLK)
SW: C112.2 L9.2 U22.9(SW)
SW0: C7.2 R7.1 U2.32(PHASE)
SW1: C43.2 R87.1 U6.32(PHASE)
SW2: C20.2 R33.1 U3.32(PHASE)
SW3: C29.2 R60.1 U4.32(PHASE)
SW4: C36.2 R73.1 U5.32(PHASE)
SW5: C50.2 R103.1 U7.32(PHASE)
SW6: C57.2 R118.1 U8.32(PHASE)
SW7: C64.2 R132.1 U9.32(PHASE)
SYNC: JP4.1 R10.2 U1.14(SYNC)
TSNS0: C17.1 C28.1 C35.1 C42.1 R28.2 U2.36(TOUT/FLT) U3.36(TOUT/FLT) U4.36(TOUT/FLT) U5.36(TOUT/FLT)
TSNS0/VDR_MON: R28.1 R292.1 U1.8(TSNS0/VDR_MON)
TSNS1: C49.1 C56.1 C63.1 C70.1 R30.1 U6.36(TOUT/FLT) U7.36(TOUT/FLT) U8.36(TOUT/FLT) U9.36(TOUT/FLT)
VDR: C12.1 C23.1 C30.1 C37.1 C44.1 C51.1 C58.1 C65.1 C87.2 C113.1 C114.1 COUT66.1 COUT67.1 D12.2(ANODE) L9.1 R5.2 R6.2 R29.2 R32.2 R58.2 R59.2 R72.2 R74.2 R86.2 R88.2 R102.2 R104.2 R116.2 R117.2 R130.2 R131.2 R166.2 R168.1 R253.2 R262.2 R268.1 U2.4(VDRV) U3.4(VDRV) U4.4(VDRV) U5.4(VDRV) U6.4(VDRV) U7.4(VDRV) U8.4(VDRV) U9.4(VDRV) U22.5(VON)
VOUT0: COUT1.1 COUT2.1 COUT3.1 COUT4.1 COUT6.1 COUT7.1 COUT8.1 COUT9.1 COUT10.1 COUT11.1 COUT12.1 COUT13.1 COUT14.1 COUT15.1 COUT16.1 COUT17.1 COUT38.1 COUT39.1 COUT40.1 COUT41.1 COUT43.2 COUT45.1 COUT46.1 COUT47.1 COUT48.1 COUT50.1 COUT57.1 COUT62.1 COUT63.1 COUT64.1 J3.1(TP) J8.1 L1.2 L2.2 L3.2 L4.2 R22.2 R50.2 R66.2 R81.2 R162.1 R183.2 R184.2 R185.2 R189.2 R190.2 R192.2 R193.2 R194.2 R195.2 R234.2
VOUT0_CFG: R39.2 U1.25(VOUT0_CFG)
VOUT1: COUT18.1 COUT19.1 COUT20.1 COUT21.1 COUT22.1 COUT23.1 COUT24.1 COUT25.1 COUT26.1 COUT27.1 COUT28.1 COUT29.1 COUT30.1 COUT31.1 COUT32.1 COUT33.1 COUT42.1 COUT44.1 COUT49.2 COUT51.1 COUT52.1 COUT53.1 COUT54.1 COUT55.1 COUT56.1 COUT58.1 COUT59.1 COUT60.1 COUT61.1 COUT65.1 J5.1(TP) J9.1 L5.2 L6.2 L7.2 L8.2 R89.2 R96.2 R110.2 R124.2 R138.2 R163.1 R183.1 R184.1 R186.2 R189.1 R190.1 R192.1 R193.1 R194.1 R195.1
VOUT1_CFG: R40.2 U1.26(VOUT1_CFG)
VSENSE0+: E3.1(A) R180.1 R234.1 U1.7(VSENSE0+)
VSENSE0-: E4.1(A) R182.1 R235.2 U1.6(VSENSE0-)
VSENSE1+: E5.1(A) R89.1 R180.2 U1.40(VSENSE1+)
VSENSE1-: E6.1(A) R98.2 R182.2 U1.41(VSENSE1-)
N03467: E16.1(A) JP4.2 R203.1
N03471: D4.2 R216.2
N03483: D4.1 Q7.3(D)
N03521: D5.1 Q8.3(D)
N03699: J13.1(FAULTB) J14.1(FAULTB) R196.1 R198.1 R210.1 R212.1
N03835: J13.13(12V) J13.14(12V) J14.13(12V) J14.14(12V) R209.2
N03887: J13.9(UNUSED) J14.9(UNUSED) R203.2
N03891: J13.7(RESETB) J14.7(RESETB)
N03895: J13.5(SHARE_CLK) J14.5(SHARE_CLK) R202.2
N03911: J13.10(UNUSED) J14.10(UNUSED) R201.2
N03923: J13.2(CTRL) J14.2(CTRL) R200.1 R204.1 R211.2 R213.2
N04115: C91.1 R205.1
N04407: C92.1 R206.1
N04463: Q4.1(G) R218.2 R220.1
N04573: D5.2 R217.2
N04715: J12.8(OUTEN_0) R211.1
N04719: J12.9(OUTEN_1) R213.1
N05931: D8.2 Q3.3(D)
N05963: D8.1 R219.1
N16783857: R169.1 R173.1 U14.3(+IN)
N16783861: C88.2 R165.1 U14.1(VOUT)
N16783881: C89.2 J10.1 Q1.3 Q2.3 R174.2 R176.2 R177.2
N16783883: C86.1 R169.2 U13.6(OUT) U14.5(V+)
N16783909: C84.1 C85.1 Q1.2 Q2.2 R162.2 R163.2
N16783985: JP2.2 JP2.3 Q1.1 Q2.1 R164.2 R172.2
N16784021: JP2.1 R165.2
N16784033: E9.1(A) R164.1
N16784069: R168.2 R171.1 U13.4(DIV)
N16784145: R166.1 U13.5(V+)
N16784254: R167.1 R170.2 U13.1(MOD)
N16784282: C88.1 R174.1 U14.4(-IN)
N16784445: R167.2 U13.3(SET)
N16784460: R173.2 R175.3(B) R178.1
N17097496: C25.2 R32.1 U3.3(VCC)
N17097514: L2.1 U3.10(SW) U3.11(SW) U3.12(SW) U3.13(SW) U3.14(SW) U3.15(SW) U3.16(SW) U3.17(SW) U3.18(SW) U3.19(SW)
N17097516: R34.2 U3.38(IOUT)
N17097563: R50.1 U3.1(VOS)
N17097565: P2.1(TP) U3.6(GL) U3.41(GL)
N17097658: R46.1 U3.37(OCSET)
N17097948: R43.2 U3.2(LGND)
N17098016: R25.2 U3.34(PWM)
N17098024: R26.1 R29.1 U3.35(EN)
N17098083: R36.2 U3.39(REFIN)
N17098193: R41.2 U1.22(RSET)
N17098209: R44.2 R279.1 R280.1 U1.12(SDI)
N17098265: R42.2 U1.27(PWM_CFG)
N17098279: R47.2 R281.1 R282.1 U1.13(SCK)
N17098423: C13.2 C15.1 R8.1 R11.2 U1.4(ISENSE0)
N17098735: R4.1 R6.1 U2.35(EN)
N17098803: R274.2 R276.2 U1.11(PGOOD0/CLKOUT)
N17098851: L1.1 U2.10(SW) U2.11(SW) U2.12(SW) U2.13(SW) U2.14(SW) U2.15(SW) U2.16(SW) U2.17(SW) U2.18(SW) U2.19(SW)
N17098877: C11.2 R3.2 U1.32(VIN)
N17099224: C14.2 R5.1 U2.3(VCC)
N17099258: R8.2 U2.38(IOUT)
N17099293: C13.1 R7.2
N17099303: R22.1 U2.1(VOS)
N17099305: P1.1(TP) U2.6(GL) U2.41(GL)
N17099384: R23.1 U2.37(OCSET)
N17099633: R21.2 U2.2(LGND)
N17099673: R2.1 U2.33(BOOST)
N17099687: R1.2 U2.34(PWM)
N17099827: R1.1 U1.5(PWM0)
N17099913: R288.1 R289.1 R290.2 U1.34(SERRb)
N17099939: R12.2 U2.39(REFIN)
N17106357: C32.2 R59.1 U4.3(VCC)
N17106363: R56.1 R58.1 U4.35(EN)
N17106383: C39.2 R74.1 U5.3(VCC)
N17106415: R70.1 R72.1 U5.35(EN)
N17106543: L3.1 U4.10(SW) U4.11(SW) U4.12(SW) U4.13(SW) U4.14(SW) U4.15(SW) U4.16(SW) U4.17(SW) U4.18(SW) U4.19(SW)
N17106588: L4.1 U5.10(SW) U5.11(SW) U5.12(SW) U5.13(SW) U5.14(SW) U5.15(SW) U5.16(SW) U5.17(SW) U5.18(SW) U5.19(SW)
N17106856: R61.2 U4.38(IOUT)
N17106905: R66.1 U4.1(VOS)
N17106907: P3.1(TP) U4.6(GL) U4.41(GL)
N17106990: R68.1 U4.37(OCSET)
N17107203: R67.2 U4.2(LGND)
N17107257: R55.2 U4.34(PWM)
N17107288: R64.2 U4.39(REFIN)
N17107411: R75.2 U5.38(IOUT)
N17107454: C38.1 R73.2
N17107460: R81.1 U5.1(VOS)
N17107462: P4.1(TP) U5.6(GL) U5.41(GL)
N17107545: R82.1 U5.37(OCSET)
N17107756: R80.2 U5.2(LGND)
N17107808: R69.2 U5.34(PWM)
N17107833: R78.2 U5.39(REFIN)
N17117380: C46.2 R88.1 U6.3(VCC)
N17117392: R84.1 R86.1 U6.35(EN)
N17117406: C53.2 R104.1 U7.3(VCC)
N17117442: R100.1 R102.1 U7.35(EN)
N17117578: L5.1 U6.10(SW) U6.11(SW) U6.12(SW) U6.13(SW) U6.14(SW) U6.15(SW) U6.16(SW) U6.17(SW) U6.18(SW) U6.19(SW)
N17117883: R90.2 U6.38(IOUT)
N17117926: C45.1 R87.2
N17117932: R96.1 U6.1(VOS)
N17117934: P5.1(TP) U6.6(GL) U6.41(GL)
N17118018: R97.1 U6.37(OCSET)
N17118238: R95.2 U6.2(LGND)
N17118290: R83.2 U6.34(PWM)
N17118319: R93.2 U6.39(REFIN)
N17118444: L6.1 U7.10(SW) U7.11(SW) U7.12(SW) U7.13(SW) U7.14(SW) U7.15(SW) U7.16(SW) U7.17(SW) U7.18(SW) U7.19(SW)
N17118446: R105.2 U7.38(IOUT)
N17118481: C52.1 R103.2
N17118495: R110.1 U7.1(VOS)
N17118497: P6.1(TP) U7.6(GL) U7.41(GL)
N17118573: R112.1 U7.37(OCSET)
N17118791: R111.2 U7.2(LGND)
N17118843: R99.2 U7.34(PWM)
N17118860: R107.2 U7.39(REFIN)
N17122803: C59.2 R117.1 U8.3(VCC)
N17122815: R114.1 R116.1 U8.35(EN)
N17122829: C67.2 R131.1 U9.3(VCC)
N17122865: R128.1 R130.1 U9.35(EN)
N17123001: L7.1 U8.10(SW) U8.11(SW) U8.12(SW) U8.13(SW) U8.14(SW) U8.15(SW) U8.16(SW) U8.17(SW) U8.18(SW) U8.19(SW)
N17123306: R119.2 U8.38(IOUT)
N17123349: C60.1 R118.2
N17123355: R124.1 U8.1(VOS)
N17123357: P7.1(TP) U8.6(GL) U8.41(GL)
N17123441: R126.1 U8.37(OCSET)
N17123661: R125.2 U8.2(LGND)
N17123713: R113.2 U8.34(PWM)
N17123742: R122.2 U8.39(REFIN)
N17123867: L8.1 U9.10(SW) U9.11(SW) U9.12(SW) U9.13(SW) U9.14(SW) U9.15(SW) U9.16(SW) U9.17(SW) U9.18(SW) U9.19(SW)
N17123869: R133.2 U9.38(IOUT)
N17123904: C66.1 R132.2
N17123918: R138.1 U9.1(VOS)
N17123920: P8.1(TP) U9.6(GL) U9.41(GL)
N17123996: R139.1 U9.37(OCSET)
N17124214: R140.2 U9.2(LGND)
N17124266: R127.2 U9.34(PWM)
N17124283: R135.2 U9.39(REFIN)
N17155250: R30.2 U1.39(TSNS1)
N17251560: C7.1 R2.2
N17277538: C20.1 R27.2
N17290745: C36.1 R71.2
N17291095: C29.1 R57.2
N17291853: R57.1 U4.33(BOOST)
N17304026: R71.1 U5.33(BOOST)
N17310142: C43.1 R85.2
N17310170: R85.1 U6.33(BOOST)
N17310658: C50.1 R101.2
N17310686: R101.1 U7.33(BOOST)
N17331859: C57.1 R115.2
N17331894: R115.1 U8.33(BOOST)
N17332381: C64.1 R129.2
N17332416: R129.1 U9.33(BOOST)
N17451472: J22.4(SCK/SCL) U18.10(B1) U19.14(S2)
N17451481: J22.5(MISO) U18.9(B2) U19.11(S3)
N17451484: J22.6(nCS) U18.8(B3)
N17451493: J22.7(MOSI/SDA) U18.7(B4) U19.3(S1)
N17451683: J22.14(GPIO_1) R270.1 U19.1(IN1) U19.8(IN4) U19.9(IN3) U19.16(IN2) U24.1(1A)
N17451801: C99.1 R261.2 U19.13(VDD)
N17452541: C100.1 R260.2 U18.1(VCC(A))
N17453120: C101.1 R259.2 U18.11(VCC(B))
N17453215: R266.1 U18.3(A2) U24.4(2Y)
N17465221: D6.2 Q5.3(D)
N17465231: D6.1 R214.1
N17465389: D7.2 Q6.3(D)
N17465399: D7.1 R215.1
N17494522: JP3.2 Q7.1(G)
N17495497: C108.1 R250.2 U22.14(SVIN)
N17495536: C110.1 CIN33.1 CIN34.1 JP1.1 R250.1 R258.1 U22.8(PVIN)
N17495675: C112.1 D1.1(CATHODE) U22.10(BOOST)
N17495693: JP1.2 U22.13(RUN)
N17495715: R251.1 U22.6(PGOOD)
N17495814: R252.2 U22.4(RT)
N17495848: C114.2 R253.1 R256.2 U22.2(VFB)
N17495854: C115.1 R255.2 U22.3(ITH)
N17495896: C116.1 R255.1
N17496758: R257.1 U22.7(MODE/SYNC)
N17534889: D9.2 Q9.3(D)
N17534899: D9.1 R233.1
N17537296: C117.1 R273.2 U24.5(VCC)
N17537515: C118.1 R272.2 U25.12(VDD)
N17537781: U23.4(A2) U25.5(MISO)
N17537790: U23.3(A1) U25.11(SPICLK)
N17537799: U23.5(A3) U25.1(\\~{SS0})
N17537898: C119.1 R264.2 U25.3(\\~{RESET})
N17538841: U23.6(A4) U25.6(MOSI)
N17539369: R266.2 U25.2(\\~{SS1})
N17539374: R265.2 U25.10(\\~{SS2})
N17539621: C120.1 R267.2 U23.1(DIR1) U23.7(DIR3) U23.8(DIR4) U23.15(VCCB) U23.16(VCCA)
N17543474: C102.1 R262.1 U20.5(Vc) U20.7(IN) U20.8(IN)
N17543530: C104.1 R242.1 U20.4(SET)
N17543606: C106.1 R263.1 U21.7(IN) U21.8(IN)
N17543664: C107.1 R246.1 U21.4(SET)
N17556057: C121.1 R274.1 R277.1
N17556758: C121.2 R277.2 R278.1 R280.2 R291.1
N17557686: R275.1 R283.1 U1.36(PGOOD1)
N17557992: C122.1 R275.2 R284.1
N17558210: C122.2 R284.2 R285.1 R287.2 R291.2
N17558253: R286.1 R287.1 U1.35(SCSb)
N17606182: R268.2 R269.1 R292.2
N17621532: C31.1 R60.2
N17644547: R27.1 U3.33(BOOST)
N17644548: C24.1 R33.2

Not connected (* = marked no-connect by the designer): J12 7(GPIO_1); J22 1(V+_(ISOPWR)) 9(EESDA) 11(EESCL); SW1 4 5 6; SW2 4 5 6; U2 31(NC); U3 31(NC); U4 31(NC); U5 31(NC); U6 31(NC); U7 31(NC); U8 31(NC); U9 31(NC); U19 4(NC) 6(S4) 7(D4) 12(NC); U20 6(NC); U21 6(NC); U25 9(\\~{INT}) 13(\\~{SS3})

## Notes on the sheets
sheet 1
- 7V - 14V
- FP1007R3-R22-R
- 1V/120A
- FP1007R3-R22-R
- VDR_MON
- *
- VERSION
- U1
- R276,R279,R281,R283,R286,R288
- R274,R275,R280,R282,R287,R289
- R277,R284
- R278,R285
- - A
- LTC3888-EUHG
- 0
- OPT
- OPT
- OPT
- - B
- LTC3888-1-EUHG
- OPT
- 0
- 31.6K
- 21K
- CONVERTER WITH POWER SYSTEM MANAGEMENT
sheet 2
- FP1007R3-R22-R
- FP1007R3-R22-R
- CONVERTER WITH POWER SYSTEM MANAGEMENT
sheet 3
- FP1007R3-R22-R
- 1V/120A
- FP1007R3-R22-R
- CONVERTER WITH POWER SYSTEM MANAGEMENT
sheet 4
- FP1007R3-R22-R
- FP1007R3-R22-R
- CONVERTER WITH POWER SYSTEM MANAGEMENT
sheet 5
- SPI INTERFACE
- SERRb
- CONVERTER WITH POWER SYSTEM MANAGEMENT
sheet 6
- 5V BIAS
- COILCRAFT
- XAL5030-472MEB
- DYNAMIC LOAD TEST CIRCUIT, FOR DEMO BOARD ONLY
- SHT 1
- VOUT0
- PULSE
- INT
- EXT
- 70Hz, 3% Duty Cycle
- SHT 1,2
- IOUT STEP
- VOUT1
- 1%
- 1%
- OPTION FOR EIGHT-PHASE CONFIGURATION CONNECTION
- CONVERTER WITH POWER SYSTEM MANAGEMENT
- BLEEDER LOADS
sheet 7
- ALL PARTS ON THIS PAGE ARE FOR DEMO BOARD ONLY, NOT NEEDED IN CUSTOMER DESIGN
- MASTER
- SLAVE
- RUN0
- TO DC1613A
- RUN1
- ON
- ON
- OFF
- OFF
- 1206
- PGOOD0
- PGOOD1
- FAULT0
- FAULT1
- ALERTb
- MASTER
- SLAVE
- CONVERTER WITH POWER SYSTEM MANAGEMENT
sheet 8
- CONVERTER WITH POWER SYSTEM MANAGEMENT
